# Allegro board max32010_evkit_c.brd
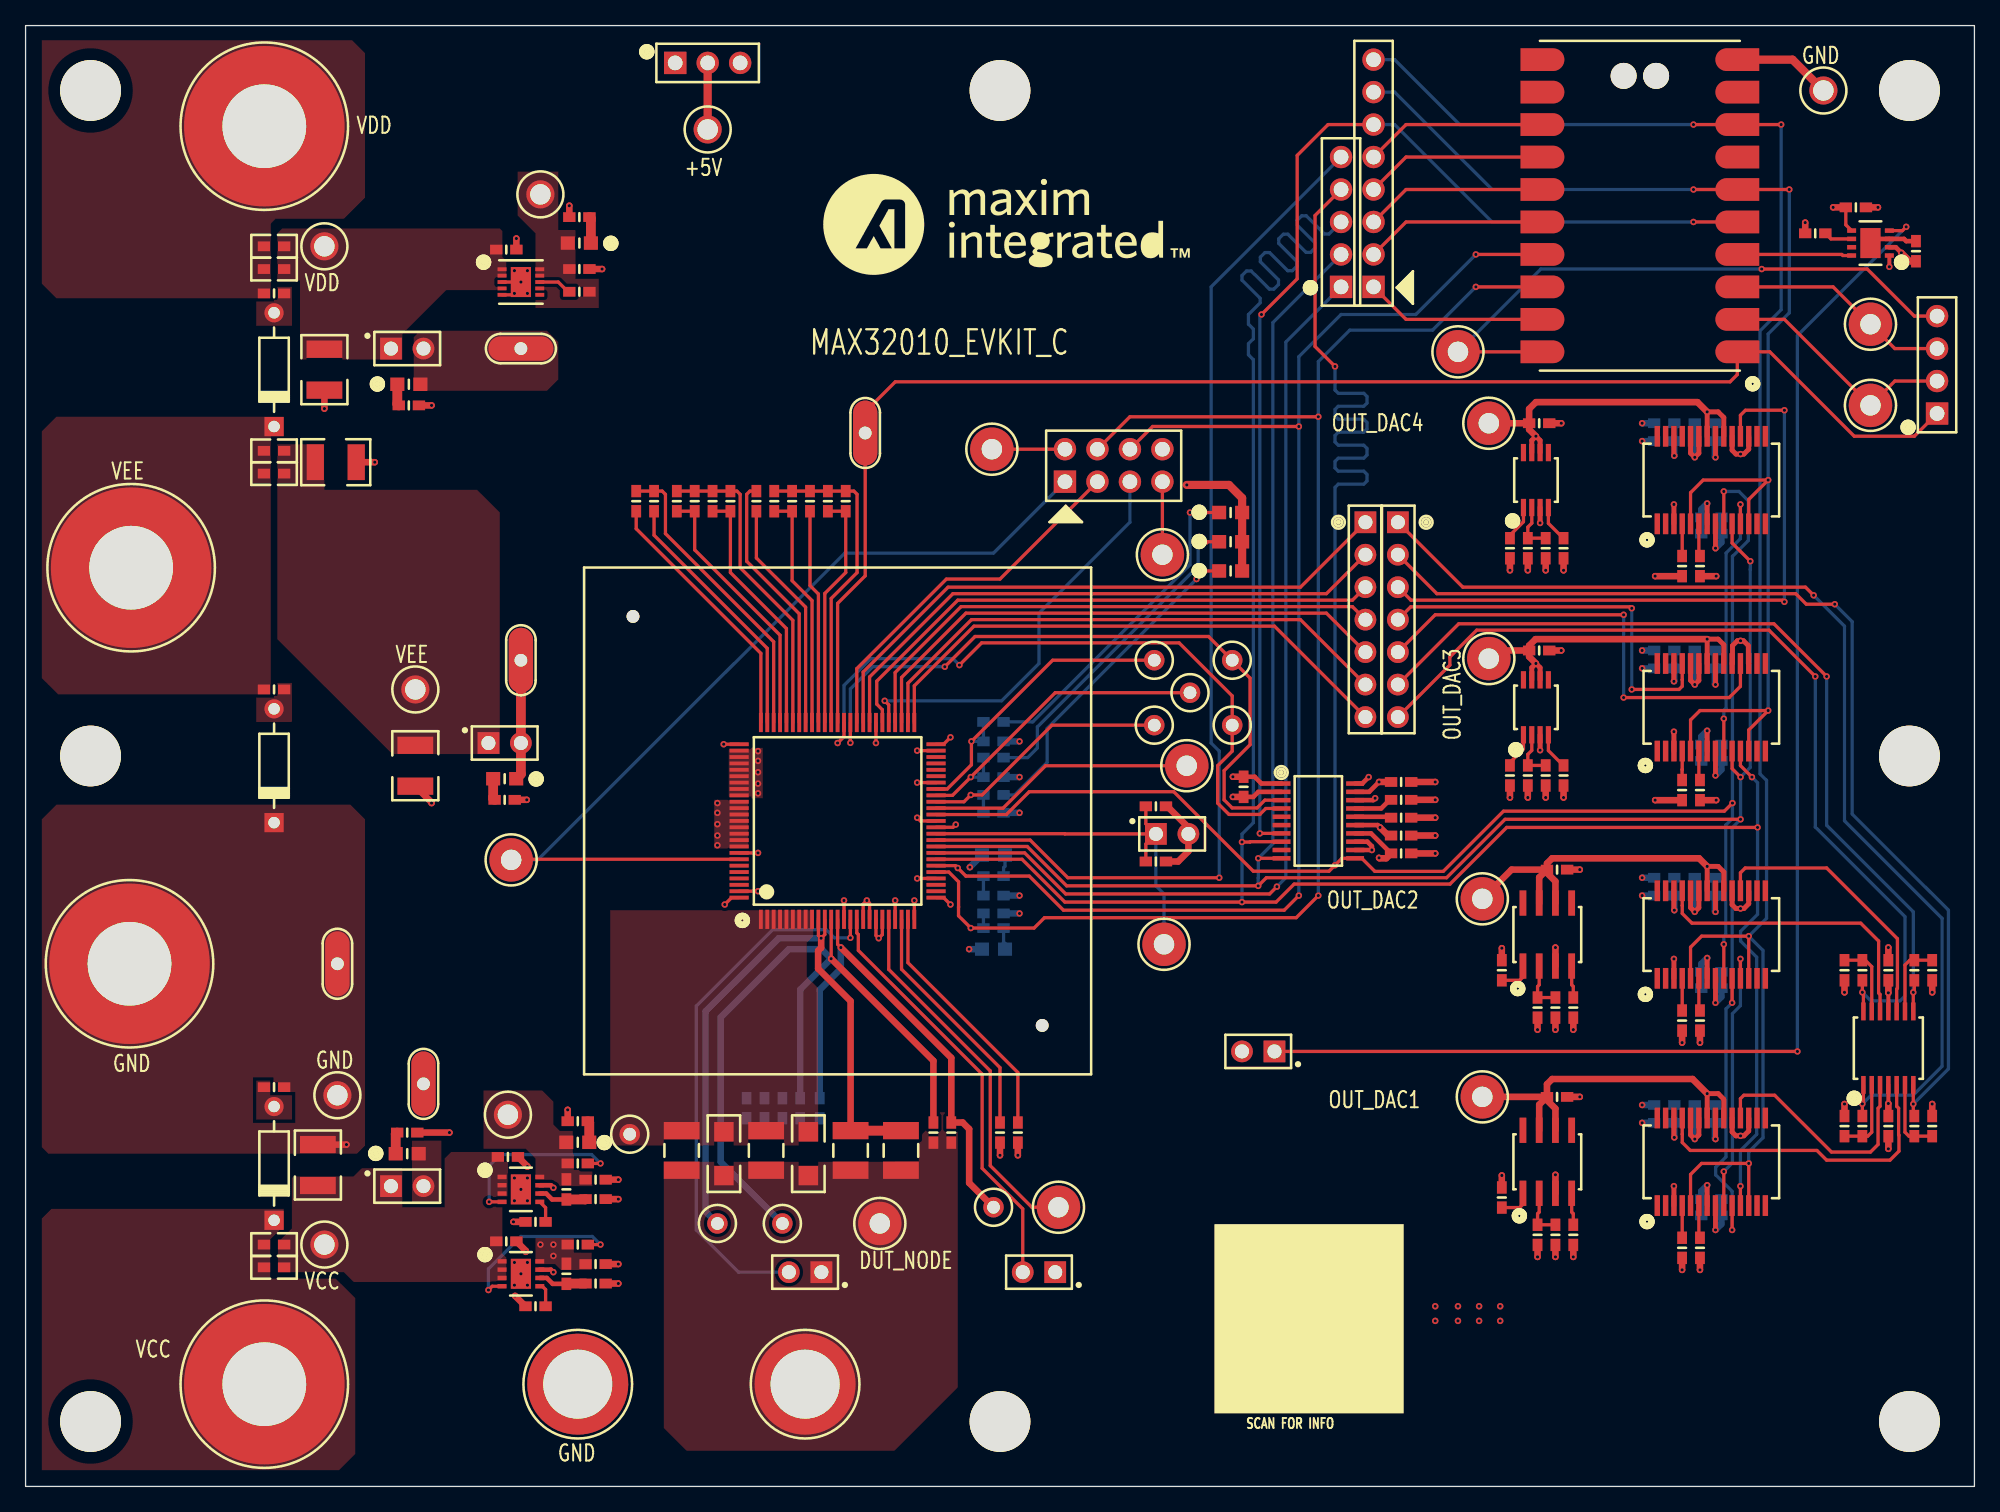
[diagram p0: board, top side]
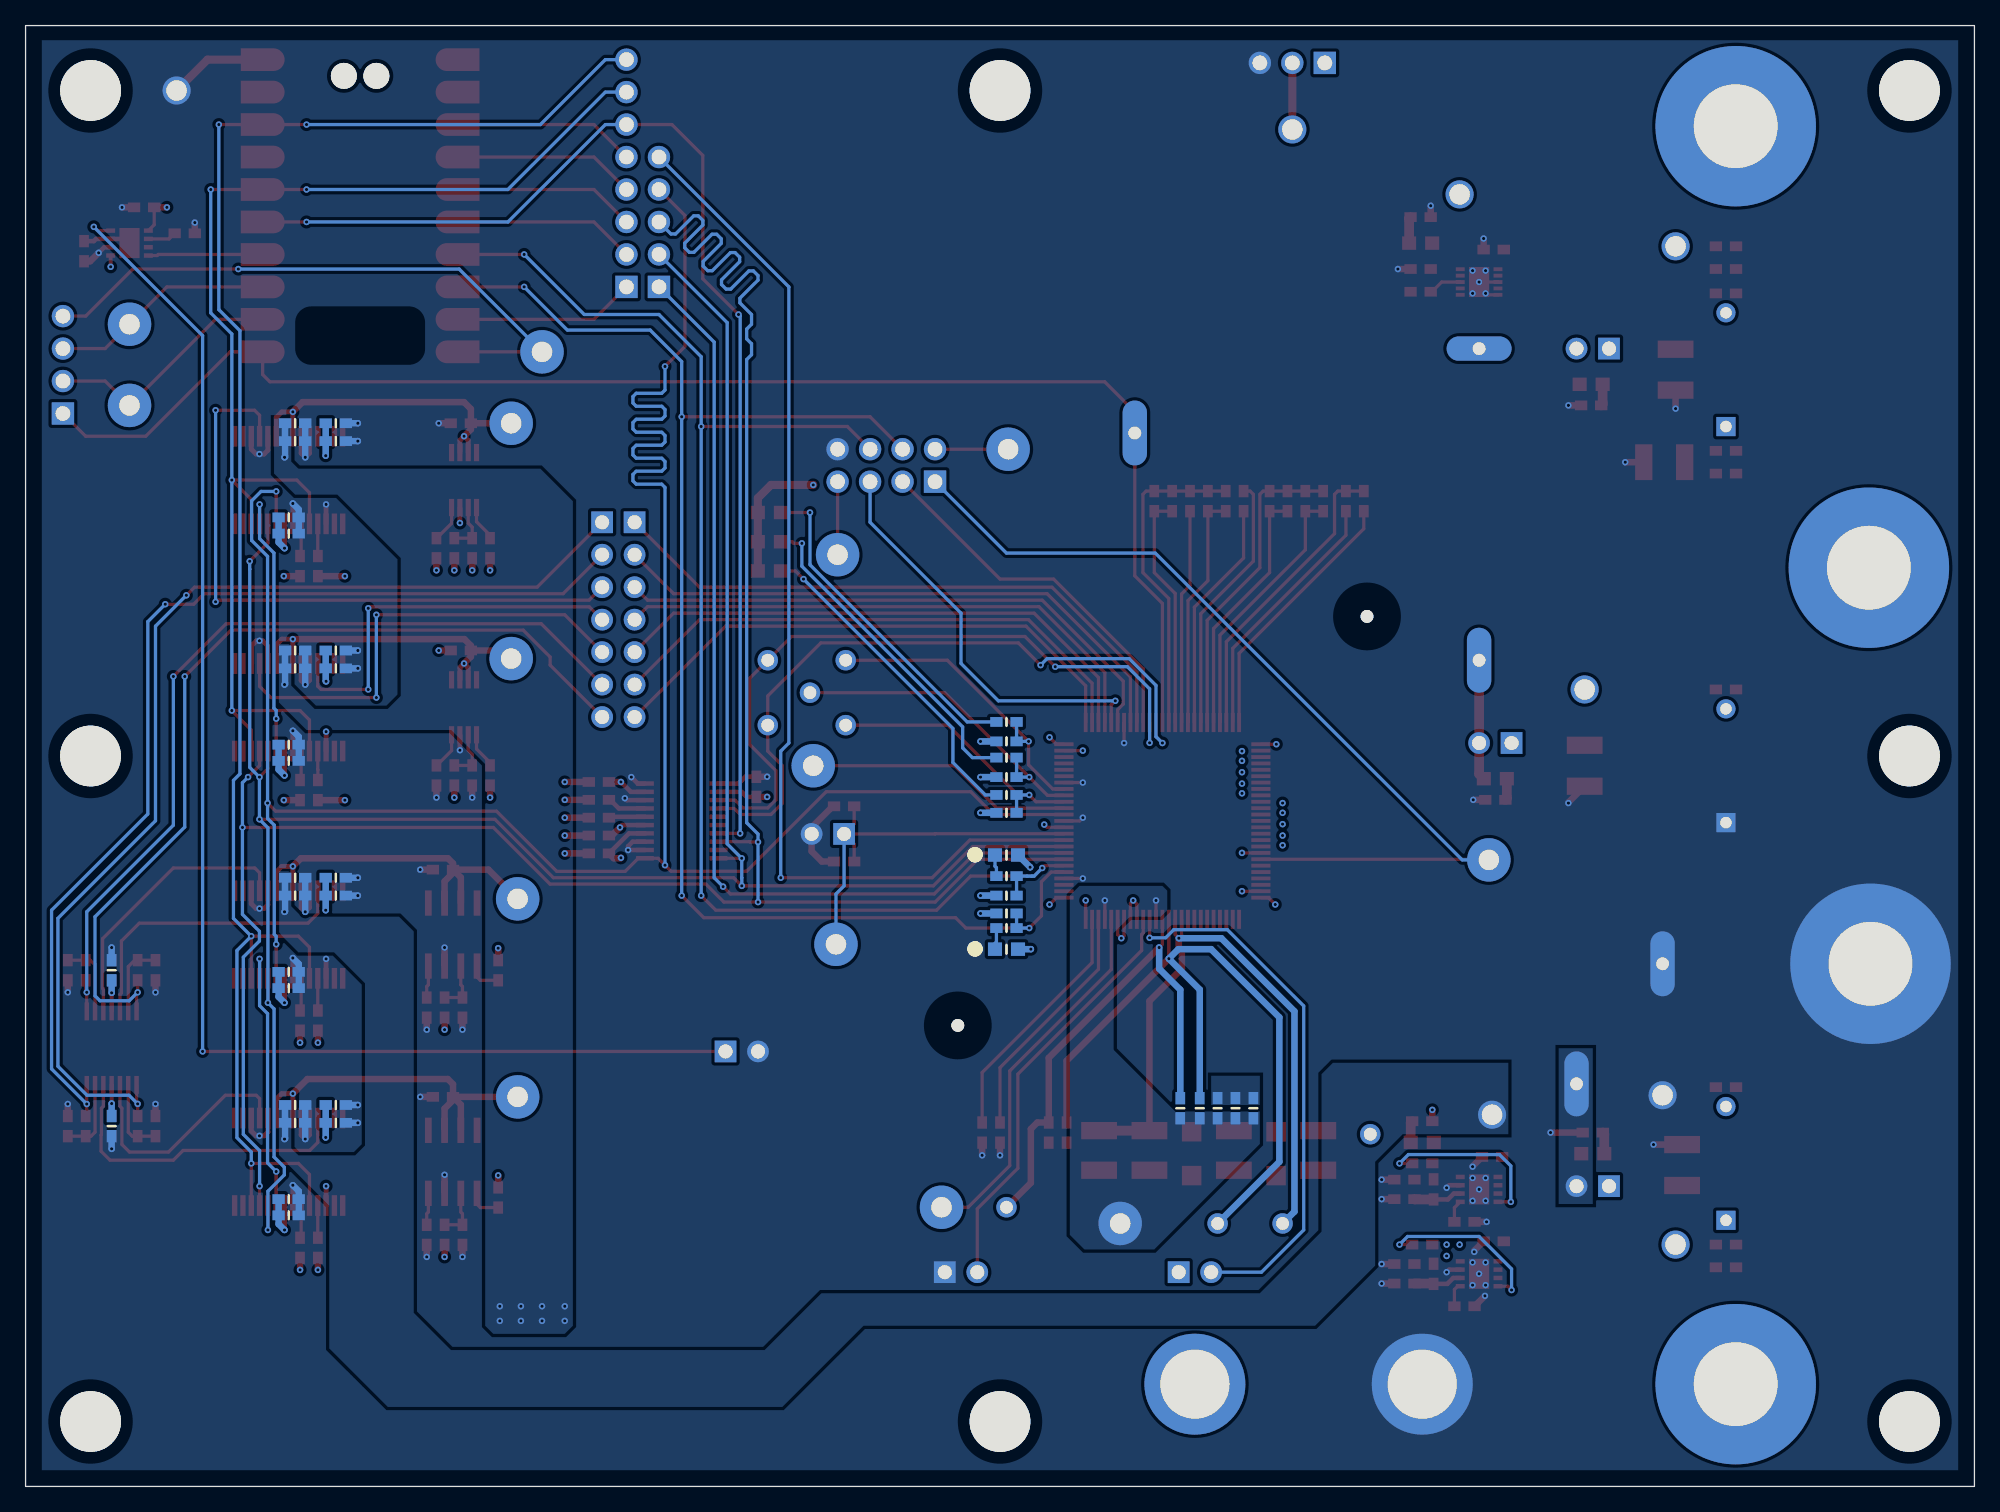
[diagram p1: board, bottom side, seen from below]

Outline 152.4 x 114.3 mm; copper layers: TOP, INTERNAL2, INTERNAL3, BOTTOM. Coordinates in mm from the lower left corner of the outline.
Outline path: rectangle 0,0 152.4,114.3

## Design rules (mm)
constraint set DEFAULT: min track width 0.254
net group MATCH: nets DIN DOUT SCLK

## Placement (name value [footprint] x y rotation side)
AMPOUT  N/A  [KEYS_5012]  37.97 49.02 0 top
C1  10UF  [1210]  22.86 25.15 270 top
C2  10UF  [1210]  30.48 56.39 270 top
C3  10UF  [1210]  24.26 80.14 180 top
C4  1UF  [0603]  37.72 25.78 180 top
C5  1000PF  [0603]  39.88 20.7 0 top
C6  4.7UF  [0603]  44.58 24 180 top
C7  1UF  [0603]  37.59 19.18 180 top
C8  1000PF  [0603]  39.88 14.1 0 top
C9  4.7UF  [0603]  44.58 17.4 180 top
C10  10UF  [0603]  37.59 96.77 180 top
C11  0.047UF  [0603]  43.31 93.47 0 top
C12  10UF  [0603]  43.31 95.25 180 top
C13  10UF  [0603]  118.24 19.68 90 top
C14  10UF  [0603]  118.24 37.47 90 top
C15  10UF  [0603]  117.47 55.63 90 top
C16  10UF  [0603]  117.47 73.41 90 top
C17  0.1UF  [0603]  115.44 22.61 270 top
C18  0.1UF  [0603]  119.76 30.48 180 top
C19  0.1UF  [0603]  115.44 40.39 270 top
C20  0.1UF  [0603]  119.76 48.26 180 top
C21  0.1UF  [0603]  116.08 55.63 90 top
C22  0.1UF  [0603]  118.36 65.41 180 top
C23  0.1UF  [0603]  116.08 73.41 90 top
C24  0.1UF  [0603]  118.36 83.19 180 top
C25  10UF  [0603]  131.83 21.21 0 bottom
C26  10UF  [0603]  131.32 29.84 0 bottom
C27  10UF  [0603]  128.14 29.84 0 bottom
C28  10UF  [0603]  131.83 38.99 0 bottom
C29  10UF  [0603]  131.32 47.62 0 bottom
C30  10UF  [0603]  128.14 47.62 0 bottom
C31  10UF  [0603]  131.83 56.77 0 bottom
C32  10UF  [0603]  131.32 65.41 0 bottom
C33  10UF  [0603]  128.14 65.41 0 bottom
C34  10UF  [0603]  131.83 74.55 0 bottom
C35  10UF  [0603]  131.32 83.19 0 bottom
C36  10UF  [0603]  128.14 83.19 0 bottom
C37  0.1UF  [0603]  131.83 22.48 0 bottom
C38  0.1UF  [0603]  131.32 28.45 0 bottom
C39  0.1UF  [0603]  128.14 28.45 0 bottom
C40  0.1UF  [0603]  131.83 40.26 0 bottom
C41  0.1UF  [0603]  131.32 46.23 0 bottom
C42  0.1UF  [0603]  128.14 46.23 0 bottom
C43  0.1UF  [0603]  131.83 58.04 0 bottom
C44  0.1UF  [0603]  131.32 64.01 0 bottom
C45  0.1UF  [0603]  128.14 64.01 0 bottom
C46  0.1UF  [0603]  131.83 75.82 0 bottom
C47  0.1UF  [0603]  131.32 81.79 0 bottom
C48  0.1UF  [0603]  128.14 81.79 0 bottom
C49  3300PF  [0603]  58.55 77.09 90 top
C50  0.022UF  [0603]  59.94 77.09 90 top
C51  330PF  [0603]  53.72 77.09 270 top
C52  4700PF  [0603]  55.12 77.09 270 top
C53  0.01UF  [0603]  61.34 77.09 90 top
C54  330PF  [0603]  50.93 77.09 270 top
C55  1500PF  [0603]  64.14 77.09 90 top
C56  4700PF  [0603]  52.32 77.09 270 top
C57  100PF  [0603]  49.15 77.09 270 top
C58  1500PF  [0603]  62.74 77.09 90 top
C59  100PF  [0603]  47.75 77.09 270 top
C60  330PF  [0603]  57.15 77.09 270 top
C61  270PF  [0603]  77.6 27.69 270 top
C62  270PF  [0603]  76.2 27.69 270 top
C63  4.7UF  [0603]  145.67 28.19 90 bottom
C64  0.1UF  [0603]  145.67 28.19 90 top
C65  4.7UF  [0603]  145.67 40.39 270 bottom
C66  0.1UF  [0603]  145.67 40.39 270 top
C67  0.1UF  [0603]  147.83 96.65 90 top
C68  0.1UF  [0603]  139.95 98.04 0 top
C69  1UF  [0603]  143.13 100.08 180 top
C70  0.1UF  [0603]  95.25 54.74 270 top
C71  0.1UF  [0603]  107.57 49.53 180 top
C72  0.1UF  [0603]  107.57 50.93 180 top
C73  0.1UF  [0603]  107.57 55.12 180 top
C74  1UF  [0603]  107.57 52.32 180 top
C75  1UF  [0603]  107.57 53.72 180 top
C76  10UF  [1210]  23.37 87.38 90 top
D1  20V  [DO-35]  19.43 25.27 90 top
D2  20V  [DO-35]  19.43 56.39 90 top
D3  20V  [DO-35]  19.43 87.38 90 top
DS1  LTST-C190CKT  [LEDC1608X80M]  94.23 76.2 0 top
DS2  LTST-C190CKT  [LEDC1608X80M]  94.23 73.91 0 top
DS3  LTST-C190CKT  [LEDC1608X80M]  94.23 71.63 0 top
DS4  LTST-C193KGKT-5A  [LEDC1608X80M]  75.69 49.4 180 bottom
DS5  LTST-C193KGKT-5A  [LEDC1608X80M]  75.69 42.04 180 bottom
DS6  LTST-C193KGKT-5A  [LEDC1608X80M]  29.84 26.04 0 top
DS8  LTST-C193KGKT-5A  [LEDC1608X80M]  37.47 55.37 180 top
DS9  LTST-C193KGKT-5A  [LEDC1608X80M]  43.18 26.92 180 top
DS10  LTST-C193KGKT-5A  [LEDC1608X80M]  43.31 97.28 180 top
DS11  LTST-C193KGKT-5A  [LEDC1608X80M]  29.97 86.23 0 top
DUT_NODE  575-4  [KEYSTONE_575]  60.96 8 90 top
EXTSEL  N/A  [KEYS_5012]  90.81 56.39 0 top
FB1  220  [0603]  19.43 18.92 0 top
FB2  220  [0603]  19.43 17.14 0 top
FB3  220  [0603]  19.43 81.03 0 top
FB4  220  [0603]  19.43 79.25 0 top
FB5  220  [0603]  19.43 95.25 0 top
FB6  220  [0603]  19.43 97.03 0 top
GND  MAXIMPAD  [EVK_MAXIMPAD]  24.38 40.89 90 top
HITEMP  N/A  [KEYS_5000]  88.27 59.56 0 top
HITMP  N/A  [KEYS_5012]  112.01 88.77 0 top
ILIMHI  N/A  [KEYS_5000]  88.27 64.64 0 top
ILIMLO  N/A  [KEYS_5000]  91.06 62.1 0 top
IMEAS  N/A  [KEYS_5002]  94.36 64.64 0 top
J1  PCC02SAAN  [SULLINS_PXC02S]  62.23 16.76 180 top
J2  PCC02SAAN  [SULLINS_PXC02S]  80.52 16.76 180 top
J3  PCC02SAAN  [SULLINS_PXC02S]  88.39 51.05 0 top
J4  PBC04DAAN  [SULLINS_PXC04DAAN]  81.28 78.61 0 top
J5  PEC03SAAN  [SULLINS_PXC03SAAN]  50.8 111.38 0 top
J6  PCC02SAAN  [SULLINS_PXC02S]  97.66 34.04 180 top
J7  PCC02SAAN  [SULLINS_PXC02S]  28.57 23.5 0 top
J8  PCC02SAAN  [SULLINS_PXC02S]  36.2 58.17 0 top
J9  PCC02SAAN  [SULLINS_PXC02S]  28.57 89.03 0 top
J10  ATS-61400D-C1-R0  [EK_ATSI_ATS-61400D-C1-R0]  63.5 52.07 0 top
J11  PBC04SAAN  [SULLINS_PXC04SAAN]  149.48 83.95 90 top
J12  PBC08SAAN  [SULLINS_PXC08SAAN]  105.41 93.85 90 top
J13  PBC05SAAN  [SULLINS_PXC05SAAN]  102.87 93.85 90 top
J14  PEC07SAAN  [SULLINS_PXC07S]  104.78 75.44 270 top
J15  PEC07SAAN  [SULLINS_PXC07S]  107.31 75.44 270 top
MH1  9032  [KEYS_9032]  5.08 109.22 180 bottom
MH2  9032  [KEYS_9032]  147.32 109.22 180 bottom
MH3  9032  [KEYS_9032]  5.08 5.08 180 bottom
MH4  9032  [KEYS_9032]  147.32 5.08 180 bottom
MH5  9032  [KEYS_9032]  76.2 5.08 180 bottom
MH6  9032  [KEYS_9032]  76.2 109.22 180 bottom
MH7  9032  [KEYS_9032]  5.08 57.15 180 bottom
MH8  9032  [KEYS_9032]  147.32 57.15 180 bottom
MISC1  3025010-03  [EVKIT_CABLES]  84.58 -8.13 0 top
NOREF  -  []  161.29 11.43 0 top
NOREF#2  -  []  92.96 5.71 0 top
NOREF#3  -  []  44.17 -25.4 0 top
NOREF#4  -  []  51.73 -3.17 0 top
NOREF#5  -  []  0 114.3 0 top
NOREF#6  -  []  74.75 150.26 0 top
NOREF#7  -  []  2.35 2.5 0 top
NOREF#8  -  []  99.06 79.41 0 top
NOREF#9  -  []  93.34 71.12 0 top
NOREF#10  -  []  152.4 0 90 top
NOREF#11  -  []  12.7 -12.7 0 top
NOREF#12  -  []  73.66 86.46 0 top
NOREF#13  -  []  6.35 -25.4 0 top
NOREF#14  -  []  66.35 98.64 0 top
NOREF#15  -  []  6.35 -25.4 180 bottom
R1  OPEN  [0603]  19.43 31.24 0 top
R2  OPEN  [0603]  19.43 62.36 180 top
R3  OPEN  [0603]  19.43 93.34 180 top
R4  390K  [0603]  42.29 23.24 270 top
R5  50K  [0603]  44.58 22.48 0 top
R6  10K  [0603]  43.18 25.27 0 top
R7  390K  [0603]  42.29 16.64 270 top
R8  50K  [0603]  44.58 15.88 0 top
R9  10K  [0603]  43.18 18.92 0 top
R10  0  [0603]  119.63 19.68 90 top
R11  0  [0603]  121.03 19.68 270 top
R12  0  [0603]  119.63 37.47 90 top
R13  0  [0603]  121.03 37.47 270 top
R14  1K  [0603]  118.87 55.63 90 top
R15  0  [0603]  120.27 55.63 270 top
R16  1K  [0603]  118.87 73.41 90 top
R17  0  [0603]  120.27 73.41 270 top
R18  22K  [0603]  130.94 18.67 90 top
R19  22K  [0603]  129.54 18.67 90 top
R20  22K  [0603]  130.94 36.45 90 top
R21  22K  [0603]  129.54 36.45 90 top
R22  22K  [0603]  130.94 54.48 90 top
R23  22K  [0603]  129.54 54.48 90 top
R24  22K  [0603]  130.94 72.01 90 top
R25  22K  [0603]  129.54 72.01 90 top
R26  OPEN  [0603]  56.39 29.59 90 bottom
R27  OPEN  [0603]  57.78 29.59 90 bottom
R28  OPEN  [0603]  59.18 29.59 90 bottom
R29  OPEN  [0603]  88.39 48.9 180 top
R30  OPEN  [0603]  88.39 53.21 0 top
R31  10  [RESC3225X65M]  51.31 26.29 270 top
R32  1.54  [1206]  54.61 26.04 270 top
R33  10  [RESC3225X65M]  57.91 26.29 270 top
R34  1.54  [1206]  61.21 26.04 270 top
R35  1K  [0603]  70.99 27.69 270 top
R36  10K  [0603]  72.39 27.69 90 top
R37  100  [RESC3225X65M]  64.52 26.29 270 top
R38  100  [RESC3225X65M]  68.45 26.29 270 top
R39  1K  [0603]  60.58 29.59 270 bottom
R40  10K  [0603]  62.1 29.59 90 bottom
R41  10K  [0603]  75.69 58.29 180 bottom
R42  1K  [0603]  75.69 59.82 180 bottom
R43  10K  [0603]  75.69 55.5 180 bottom
R44  1K  [0603]  75.69 57.02 180 bottom
R45  10K  [0603]  75.69 52.7 180 bottom
R46  10K  [0603]  75.69 46.23 180 bottom
R47  1K  [0603]  75.69 54.1 180 bottom
R48  1K  [0603]  75.69 47.75 180 bottom
R49  10K  [0603]  75.69 44.83 180 bottom
R50  1K  [0603]  75.69 43.69 180 bottom
R51  3.3K  [0603]  29.84 27.69 0 top
R53  1K  [0603]  29.97 84.58 0 top
R54  2.7K  [0603]  43.18 28.57 180 top
R55  1K  [0603]  43.31 99.31 180 top
R56  3.48K  [0603]  149.1 28.19 270 top
R57  3.48K  [0603]  142.24 28.19 270 top
R58  2K  [0603]  147.7 28.19 90 top
R59  2K  [0603]  143.64 28.19 90 top
R60  3.48K  [0603]  149.1 40.39 90 top
R61  3.48K  [0603]  142.24 40.39 90 top
R62  2K  [0603]  147.7 40.39 270 top
R63  2K  [0603]  143.64 40.39 270 top
R68  2.7K  [0603]  37.47 53.72 0 top
RA  N/A  [KEYS_5000]  47.24 27.56 90 top
RB  N/A  [KEYS_5000]  54.1 20.57 90 top
RC  N/A  [KEYS_5000]  59.18 20.57 90 top
RD  N/A  [KEYS_5000]  75.69 21.84 90 top
SU1  NPC02SXON-RC  [EVKIT_SHUNT]  140.64 -23.73 0 top
SU2  NPC02SXON-RC  [EVKIT_SHUNT]  121.87 -23.73 0 top
SU3  NPC02SXON-RC  [EVKIT_SHUNT]  112.49 -23.73 0 top
SU4  NPC02SXON-RC  [EVKIT_SHUNT]  103.11 -23.73 0 top
SU5  NPC02SXON-RC  [EVKIT_SHUNT]  93.73 -23.73 0 top
SU6  NPC02SXON-RC  [EVKIT_SHUNT]  74.97 -23.73 0 top
SU7  NPC02SXON-RC  [EVKIT_SHUNT]  65.59 -23.73 0 top
SU8  NPC02SXON-RC  [EVKIT_SHUNT]  84.35 -23.73 0 top
SU9  NPC02SXON-RC  [EVKIT_SHUNT]  131.26 -23.73 0 top
SU10  NPC02SXON-RC  [EVKIT_SHUNT]  65.59 -29.12 0 top
SU11  NPC02SXON-RC  [EVKIT_SHUNT]  74.97 -29.12 0 top
SU12  NPC02SXON-RC  [EVKIT_SHUNT]  84.35 -29.12 0 top
SU13  NPC02SXON-RC  [EVKIT_SHUNT]  93.73 -29.12 0 top
SU14  NPC02SXON-RC  [EVKIT_SHUNT]  103.11 -29.12 0 top
SU15  NPC02SXON-RC  [EVKIT_SHUNT]  112.49 -29.12 0 top
SU16  NPC02SXON-RC  [EVKIT_SHUNT]  121.87 -29.12 0 top
SU17  NPC02SXON-RC  [EVKIT_SHUNT]  131.26 -29.12 0 top
SU18  NPC02SXON-RC  [EVKIT_SHUNT]  140.64 -29.12 0 top
SU19  NPC02SXON-RC  [EVKIT_SHUNT]  150.02 -29.12 0 top
SU20  NPC02SXON-RC  [EVKIT_SHUNT]  159.4 -29.12 0 top
SU21  NPC02SXON-RC  [EVKIT_SHUNT]  168.78 -29.12 0 top
TEMP  MAXIMPAD  [EVK_MAXIMPAD]  65.66 82.42 90 top
TP1  3267  [POMONA_3267]  18.67 8 0 top
TP2  3267  [POMONA_3267]  8.13 40.89 0 top
TP3  3267  [POMONA_3267]  8.26 71.88 180 top
TP4  3267  [POMONA_3267]  18.67 106.43 180 top
TP5  N/A  [KEYS_5005]  23.37 18.92 0 top
TP6  N/A  [KEYS_5006]  24.38 30.61 0 top
TP7  N/A  [KEYS_5006]  30.48 62.36 0 top
TP8  N/A  [KEYS_5005]  23.37 97.03 0 top
TP9  N/A  [KEYS_5012]  113.92 30.48 90 top
TP10  N/A  [KEYS_5012]  113.92 45.97 90 top
TP11  N/A  [KEYS_5012]  114.43 64.77 90 top
TP12  N/A  [KEYS_5012]  114.43 83.19 90 top
TP13  N/A  [KEYS_5012]  66.8 20.57 90 top
TP14  575-4  [KEYSTONE_575]  43.18 8 90 top
TP17  N/A  [KEYS_5012]  144.27 84.58 0 top
TP18  N/A  [KEYS_5012]  144.27 90.93 0 top
TP19  N/A  [KEYS_5012]  88.9 72.9 0 top
TP20  N/A  [KEYS_5012]  75.56 81.15 0 top
TP21  N/A  [KEYS_5006]  140.59 109.22 0 top
TP22  N/A  [KEYS_5005]  53.34 106.17 0 top
U1  MAX16910CATA8+  [MAXIM_90-0059]  38.73 23.24 0 top
U2  MAX16910CATA8+  [MAXIM_90-0059]  38.73 16.64 0 top
U3  MAX38903AATB+  [MAXIM_90-0003]  38.73 94.23 0 top
U4  MAX6126AASA50+  [MAXIM_90-0096]  119 25.4 90 top
U5  MAX6126AASA50+  [MAXIM_90-0096]  119 43.18 90 top
U6  MAX6126B21+  [MAXIM_90-0092]  118.11 60.96 90 top
U7  MAX6126B21+  [MAXIM_90-0092]  118.11 78.74 90 top
U8  MAX5322EAI+  [MAXIM_90-0095]  131.83 25.4 90 top
U9  MAX5322EAI+  [MAXIM_90-0095]  131.83 43.18 90 top
U10  MAX5322EAI+  [MAXIM_90-0095]  131.83 60.96 90 top
U11  MAX5322EAI+  [MAXIM_90-0095]  131.83 78.74 90 top
U12  MAX32010  [MAXIM_90-0159]  63.5 52.07 90 top
U13  MAX32625PICO  [MOD_MAX32625PICO_20P]  126.24 100.2 180 top
U14  MAX44245AUD+  [MAXIM_90-0113]  145.67 34.29 90 top
U15  MAX14759ETA+  [MAXIM_90-0059]  144.27 97.28 180 top
U16  MAX1033BEUP+  [MAXIM_90-0116]  101.09 52.07 0 top
VCC  MAXIMPAD  [EVK_MAXIMPAD]  31.11 31.5 90 top
VDAC  N/A  [KEYS_5005]  37.72 29.08 0 top
VDD  MAXIMPAD  [EVK_MAXIMPAD]  38.73 89.03 180 top
VEE  MAXIMPAD  [EVK_MAXIMPAD]  38.73 64.64 90 top
VL  N/A  [KEYS_5005]  40.26 101.09 0 top
VMEAS  N/A  [KEYS_5002]  94.36 59.56 0 top
VRXP  N/A  [KEYS_5012]  80.77 21.84 90 top
VTHR  N/A  [KEYS_5012]  89.03 42.42 0 top

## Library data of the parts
AMPOUT EXTSEL HITMP TP9-TP13 TP17-TP20 VRXP VTHR = TP: part number: TP_TP-KEYS_5012,N/A,02-TPMINI5012-00
C1-C3 C76 = CAP_NP: alternate symbols: CAPC3225X270L,CAP1210-NOT_FOR_TEST; part number: CAP_NP_1210CAP-1210,10UF,20-0010U-G9
C4 C7 C69 C74 C75 = CAP_NP: alternate symbols: 0603_NOSILK,CAPC1608X90L,CAP0603-NOT_FOR_TEST; part number: CAP_NP_0603CAP-0603,1UF,20-0001U-P6
C5 C8 = CAP_NP: alternate symbols: 0603_NOSILK,CAPC1608X90L,CAP0603-NOT_FOR_TEST; part number: CAP_NP_0603CAP-0603,1000PF,20-1000P-E4
C6 C9 C63 C65 = CAP_NP: alternate symbols: 0603_NOSILK,CAPC1608X90L; part number: CAP_NP_0603CAP-0603,4.7UF,20-004U7-L3
C10 C12-C16 C25-C36 = CAP_NP: alternate symbols: 0603_NOSILK,CAPC1608X90L,CAP0603-NOT_FOR_TEST; part number: CAP_NP_0603CAP-0603,10UF,20-0010U-P7
C11 = CAP_NP: alternate symbols: 0603_NOSILK,CAPC1608X90L,CAP0603-NOT_FOR_TEST; part number: CAP_NP_0603CAP-0603,0.047UF,20-0U047-91
C17-C24 C37-C48 C64 C66-C68 C70-C73 = CAP_NP: alternate symbols: 0603_NOSILK,CAPC1608X90L,CAP0603-NOT_FOR_TEST; part number: CAP_NP_0603CAP-0603,0.1UF,20-000U1-EA01
C49 = CAP_NP: alternate symbols: 0603_NOSILK,CAPC1608X90L; part number: CAP_NP_0603CAP-0603,3300PF,20-3300P-BA63
C50 = CAP_NP: alternate symbols: 0603_NOSILK,CAPC1608X90L,CAP0603-NOT_FOR_TEST; part number: CAP_NP_0603CAP-0603,0.022UF,20-0U022-91
C51 C54 C60 = CAP_NP: alternate symbols: 0603_NOSILK,CAPC1608X90L; part number: CAP_NP_0603CAP-0603,330PF,20-0330P-14B
C52 C56 = CAP_NP: alternate symbols: (0603_NOSILK); part number: CAP_NP_0603CAP-0603,4700PF,20-4700P-91
C53 = CAP_NP: alternate symbols: 0603_NOSILK,CAPC1608X90L; part number: CAP_NP_0603CAP-0603,0.01UF,20-00U01-B70
C55 C58 = CAP_NP: alternate symbols: (0603_NOSILK); part number: CAP_NP_0603CAP-0603,1500PF,20-1500P-91
C57 C59 = CAP_NP: alternate symbols: 0603_NOSILK,CAPC1608X90L; part number: CAP_NP_0603CAP-0603,100PF,20-0100P-15
C61 C62 = CAP_NP: alternate symbols: (0603_NOSILK); part number: CAP_NP_0603CAP-0603,270PF,20-0270P-77
D1-D3 = DIO_ZENER: part number: DIO_ZENER_DO-35-DO-35,20V,30-1N5250B-00
DS1-DS3 = LED: part number: LED_LEDC1608X80M-LEDC1608X80M,LTST-C190CKT,30-LTSTC190CKT-00
DS4-DS6 DS8-DS11 = LED: part number: LED_LEDC1608X80M-LEDC1608X80M,LTST-C193KGKT-5A,30-LTSTC193KGKT5A-00
DUT_NODE TP14 = BANANA: part number: BANANA_TMR-KEYSTONE_575,575-4,02-57541P-01
FB1-FB6 = FERRITEBEAD: alternate symbols: INDC1608X65L; part number: FERRITEBEAD_0603-0603,220,51-00220-0AV
GND TEMP VCC VDD VEE = EVK_MAXIMPAD: alternate symbols: EVK_MAXIMPAD_ALT; part number: EVK_MAXIMPAD_MISC-EVK_MAXIMPAD,MAXIMPAD,01-9020BUSS20AWG-00
HITEMP ILIMHI ILIMLO RA RB RC RD = TP: part number: TP_TP-KEYS_5000,N/A,02-TPMINI5000-00
IMEAS VMEAS = TP: part number: TP_TP-KEYS_5002,N/A,02-TPMINI5002-00
J1-J3 J6-J9 = HEADER_2P: part number: HEADER_2P_PXC02S-SULLINS_PXC02S,PCC02SAAN,01-PCC02SAAN2P-21
J4 = HEADER_4P_X_2R: part number: HEADER_4P_X_2R_TH-SULLINS_PXC04DAAN,PBC04DAAN,01-PBC04DAAN8P-21
J5 = HEADER_3P: alternate symbols: SULLINS_PXC03SL; part number: HEADER_3P_TH-SULLINS_PXC03SAAN,PEC03SAAN,01-PEC03SAAN3P-21
J10 = EK_HEAT_SINK: part number: EK_HEAT_SINK_ASSEMBLY-EK_ATSI_ATS-61400D-C1-R0,ATS-61400D-C1-R0,EH111000005579
J11 = HEADER_4P: part number: HEADER_4P_TH-SULLINS_PXC04SAAN,PBC04SAAN,01-PBC04SAAN4P-21
J12 = HEADER_8P: part number: HEADER_8P_TH-SULLINS_PXC08SAAN,PBC08SAAN,01-PBC08SAAN8P-21
J13 = HEADER_5P: part number: HEADER_5P_TH-SULLINS_PXC05SAAN,PBC05SAAN,01-PBC05SAAN5P-21
J14 J15 = HEADER_7P: part number: HEADER_7P_PXC07S-SULLINS_PXC07S,PEC07SAAN,01-PEC07SAAN7P-21
MH1-MH8 = SPACER: part number: SPACER_MECH-02-SOM35016H-00,9032,KEYS_9032
MISC1 = CABLES: part number: CABLES_MISC-01-302501003-10,3025010-03,EVKIT_CABLES
R1-R3 R26-R30 = EVK_GENERIC_RESISTORS: alternate symbols: 0603_NOSILK,RESC1608X90L; part number: EVK_GENERIC_RESISTORS_0603RES-0603,N/A
R4 R7 = RES: alternate symbols: (0603_NOSILK); part number: RES_0603RES-0603,390K,80-0390K-53
R5 R8 = RES: alternate symbols: 0603_NOSILK,RESC1608X90L; part number: RES_0603RES-0603,50K,80-0050K-AA99
R6 R9 R36 R40 = RES: alternate symbols: 0603_NOSILK,RESC1608X90L; part number: RES_0603RES-0603,10K,80-0010K-24
R10-R13 R15 R17 = RES: alternate symbols: 0603_NOSILK,RESC1608X90L; part number: RES_0603RES-0603,0,80-0000R-AA6
R14 R16 R35 R39 R42 R44 R47 R48 R50 = RES: alternate symbols: 0603_NOSILK,RESC1608X90L; part number: RES_0603RES-0603,1K,80-0001K-24
R18-R25 = RES: alternate symbols: (0603_NOSILK); part number: RES_0603RES-0603,22K,80-0022K-24
R31 R33 = RES: alternate symbols: RESC3225X70L; part number: RES_1210RES-RESC3225X65M,10,80-0010R-DA02
R32 R34 = RES: alternate symbols: RESC3116X60L; part number: RES_1206RES-1206,1.54,ER111000003584
R37 R38 = RES: alternate symbols: RESC3225X70L; part number: RES_1210RES-RESC3225X65M,100,80-0100R-BA01
R41 R43 R45 R46 R49 = RES: alternate symbols: (0603_NOSILK); part number: RES_0603RES-0603,10K,80-0010K-77
R51 = RES: alternate symbols: 0603_NOSILK,RESC1608X90L; part number: RES_0603RES-0603,3.3K,80-003K3-24
R53 R55 = RES: alternate symbols: 0603_NOSILK,RESC1608X90L; part number: RES_0603RES-0603,1K,80-0001K-53
R54 R68 = RES: alternate symbols: 0603_NOSILK,RESC1608X90L; part number: RES_0603RES-0603,2.7K,80-002K7-24
R56 R57 R60 R61 = RES: alternate symbols: 0603_NOSILK,RESC1608X90L; part number: RES_0603RES-0603,3.48K,80-03K48-AA4
R58 R59 R62 R63 = RES: alternate symbols: (0603_NOSILK); part number: RES_0603RES-0603,2K,80-0002K-19
SU1-SU21 = SHUNT: part number: SHUNT_SHUNT_2P-01-NPC02SXON2P-24,NPC02SXON-RC,EVKIT_SHUNT
TP1-TP4 = BANANA: alternate symbols: POMONA_3267_LUG_HEAD,POMONA_3267_LUG_NUT; part number: BANANA_3267-POMONA_3267,3267,01-32671P-80
TP5 TP8 TP22 VDAC VL = TP: part number: TP_TP-KEYS_5005,N/A,02-TPCOMP5005-00
TP6 TP7 TP21 = TP: part number: TP_TP-KEYS_5006,N/A,02-TPCOMP5006-00
U1 U2 = MAX16910: part number: MAX16910_TDFN8-EP-MAXIM_90-0059,MAX16910CATA8+,10-MAX16910CATA8-T
U3 = EK_MAX38903: part number: EK_MAX38903_TDFN10-EP-MAXIM_90-0003,MAX38903AATB+,N/A
U4 U5 = MAX6126: part number: MAX6126_SOIC-MAXIM_90-0096,MAX6126AASA50+,10-MAX6126AASA50-S
U6 U7 = MAX6126: part number: MAX6126_UMAX8-MAXIM_90-0092,MAX6126B21+,10-MAX6126B21-U
U8-U11 = MAX5322: part number: MAX5322_SSOP28-MAXIM_90-0095,MAX5322EAI+,10-MAX5322EAI-A
U12 = EK_MAX32010: part number: EK_MAX32010_TQFP100-MAXIM_90-0159,MAX32010,N/A
U13 = MAX32625PICO: part number: MAX32625PICO_MOD_20P-MOD_MAX32625PICO_20P,MAX32625PICO,10-MODMAX32625PICO-00
U14 = MAX44245: part number: MAX44245_SPLIT_TSSOP14-MAXIM_90-0113,MAX44245AUD+,10-MAX44245AUD-U
U15 = MAX14759: part number: MAX14759_TDFN8-EP-MAXIM_90-0059,MAX14759ETA+,10-MAX14759ETA-T
U16 = MAX1033: part number: MAX1033_TSSOP-MAXIM_90-0116,MAX1033BEUP+,10-MAX1033BEUP-U

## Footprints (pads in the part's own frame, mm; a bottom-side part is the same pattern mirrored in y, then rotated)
0603
  rect 0.965x0.762 smd: 1(-0.787,0) 2(0.787,0)
1206
  rect 1.524x1.524 smd: 1(-1.714,0) 2(1.714,0)
1210
  rect 1.35x2.8 smd: 1(-1.6,0) 2(1.6,0)
DO-35
  round 1.5 hole 0.9: A(4.45,0)
  rect 1.5x1.5 hole 0.9: C(-4.45,0)
EK_ATSI_ATS-61400D-C1-R0
  round 1 hole 4.3 unplated: (-16,16) (16,-16)
EVK_MAXIMPAD
  oval 5.08x1.905 hole 1: 1(0,0)
KEYS_5000
  round 1.6 hole 1: 1(0,0)
KEYS_5002
  round 1.6 hole 1: 1(0,0)
KEYS_5005
  round 2.2 hole 1.6: 1(0,0)
KEYS_5006
  round 2.2 hole 1.6: 1(0,0)
KEYS_5012
  round 3.4 hole 1.6: 1(0,0)
KEYS_9032
  round 4.75 hole 4.75 unplated: (0,0)
KEYSTONE_575
  round 7.9 hole 5.4: 1(0,0)
LEDC1608X80M
  rect 1.1x1.05 smd: A(0.9,0) K(-0.9,0)
MAXIM_90-0003
  rect 0.7x0.3 smd: 1(-1.475,1) 2(-1.475,0.5) 3(-1.475,0) 4(-1.475,-0.5) 5(-1.475,-1) 6(1.475,-1) 7(1.475,-0.5) 8(1.475,0) 9(1.475,0.5) 10(1.475,1)
  rect 1.58x2.35 smd: 11(0,0)
MAXIM_90-0059
  rect 0.7x0.35 smd: 1(-1.475,0.975) 2(-1.475,0.325) 3(-1.475,-0.325) 4(-1.475,-0.975) 5(1.475,-0.975) 6(1.475,-0.325) 7(1.475,0.325) 8(1.475,0.975)
  rect 1.58x2.35 smd: 9(0,0)
MAXIM_90-0092
  rect 1.35x0.4 smd: 1(-2.15,0.975) 2(-2.15,0.325) 3(-2.15,-0.325) 4(-2.15,-0.975) 5(2.15,-0.975) 6(2.15,-0.325) 7(2.15,0.325) 8(2.15,0.975)
MAXIM_90-0095
  rect 1.62x0.42 smd: 1(-3.425,4.225) 2(-3.425,3.575) 3(-3.425,2.925) 4(-3.425,2.275) 5(-3.425,1.625) 6(-3.425,0.975) 7(-3.425,0.325) 8(-3.425,-0.325) 9(-3.425,-0.975) 10(-3.425,-1.625) 11(-3.425,-2.275) 12(-3.425,-2.925) 13(-3.425,-3.575) 14(-3.425,-4.225) 15(3.425,-4.225) 16(3.425,-3.575) 17(3.425,-2.925) 18(3.425,-2.275) 19(3.425,-1.625) 20(3.425,-0.975) 21(3.425,-0.325) 22(3.425,0.325) 23(3.425,0.975) 24(3.425,1.625) 25(3.425,2.275) 26(3.425,2.925) 27(3.425,3.575) 28(3.425,4.225)
MAXIM_90-0096
  rect 1.98x0.53 smd: 1(-2.465,1.905) 2(-2.465,0.635) 3(-2.465,-0.635) 4(-2.465,-1.905) 5(2.465,-1.905) 6(2.465,-0.635) 7(2.465,0.635) 8(2.465,1.905)
MAXIM_90-0113
  rect 1.4x0.35 smd: 1(-2.875,1.95) 2(-2.875,1.3) 3(-2.875,0.65) 4(-2.875,0) 5(-2.875,-0.65) 6(-2.875,-1.3) 7(-2.875,-1.95) 8(2.875,-1.95) 9(2.875,-1.3) 10(2.875,-0.65) 11(2.875,0) 12(2.875,0.65) 13(2.875,1.3) 14(2.875,1.95)
MAXIM_90-0116
  rect 1.4x0.35 smd: 1(-2.875,2.925) 2(-2.875,2.275) 3(-2.875,1.625) 4(-2.875,0.975) 5(-2.875,0.325) 6(-2.875,-0.325) 7(-2.875,-0.975) 8(-2.875,-1.625) 9(-2.875,-2.275) 10(-2.875,-2.925) 11(2.875,-2.925) 12(2.875,-2.275) 13(2.875,-1.625) 14(2.875,-0.975) 15(2.875,-0.325) 16(2.875,0.325) 17(2.875,0.975) 18(2.875,1.625) 19(2.875,2.275) 20(2.875,2.925)
MAXIM_90-0159
  rect 1.5x0.3 smd: 1(-7.7,6) 2(-7.7,5.5) 3(-7.7,5) 4(-7.7,4.5) 5(-7.7,4) 6(-7.7,3.5) 7(-7.7,3) 8(-7.7,2.5) 9(-7.7,2) 10(-7.7,1.5) 11(-7.7,1) 12(-7.7,0.5) 13(-7.7,0) 14(-7.7,-0.5) 15(-7.7,-1) 16(-7.7,-1.5) 17(-7.7,-2) 18(-7.7,-2.5) 19(-7.7,-3) 20(-7.7,-3.5) 21(-7.7,-4) 22(-7.7,-4.5) 23(-7.7,-5) 24(-7.7,-5.5) 25(-7.7,-6) 51(7.7,-6) 52(7.7,-5.5) 53(7.7,-5) 54(7.7,-4.5) 55(7.7,-4) 56(7.7,-3.5) 57(7.7,-3) 58(7.7,-2.5) 59(7.7,-2) 60(7.7,-1.5) 61(7.7,-1) 62(7.7,-0.5) 63(7.7,0) 64(7.7,0.5) 65(7.7,1) 66(7.7,1.5) 67(7.7,2) 68(7.7,2.5) 69(7.7,3) 70(7.7,3.5) 71(7.7,4) 72(7.7,4.5) 73(7.7,5) 74(7.7,5.5) 75(7.7,6)
  rect 0.3x1.5 smd: 26(-6,-7.7) 27(-5.5,-7.7) 28(-5,-7.7) 29(-4.5,-7.7) 30(-4,-7.7) 31(-3.5,-7.7) 32(-3,-7.7) 33(-2.5,-7.7) 34(-2,-7.7) 35(-1.5,-7.7) 36(-1,-7.7) 37(-0.5,-7.7) 38(0,-7.7) 39(0.5,-7.7) 40(1,-7.7) 41(1.5,-7.7) 42(2,-7.7) 43(2.5,-7.7) 44(3,-7.7) 45(3.5,-7.7) 46(4,-7.7) 47(4.5,-7.7) 48(5,-7.7) 49(5.5,-7.7) 50(6,-7.7) 76(6,7.7) 77(5.5,7.7) 78(5,7.7) 79(4.5,7.7) 80(4,7.7) 81(3.5,7.7) 82(3,7.7) 83(2.5,7.7) 84(2,7.7) 85(1.5,7.7) 86(1,7.7) 87(0.5,7.7) 88(0,7.7) 89(-0.5,7.7) 90(-1,7.7) 91(-1.5,7.7) 92(-2,7.7) 93(-2.5,7.7) 94(-3,7.7) 95(-3.5,7.7) 96(-4,7.7) 97(-4.5,7.7) 98(-5,7.7) 99(-5.5,7.7) 100(-6,7.7)
MOD_MAX32625PICO_20P
  round 2.032 hole 2.032 unplated: (-1.27,-10.16) (1.27,-10.16)
  custom 0.445x0.445 smd: 1(-7.62,11.43) 2(-7.62,8.89) 3(-7.62,6.35) 4(-7.62,3.81) 5(-7.62,1.27) 6(-7.62,-1.27) 7(-7.62,-3.81) 8(-7.62,-6.35) 9(-7.62,-8.89) 10(-7.62,-11.43) 11(7.62,-11.43) 12(7.62,-8.89) 13(7.62,-6.35) 14(7.62,-3.81) 15(7.62,-1.27) 16(7.62,1.27) 17(7.62,3.81) 18(7.62,6.35) 19(7.62,8.89) 20(7.62,11.43)
POMONA_3267
  round 12.55 hole 6.55: 1(0,0)
RESC3225X65M
  rect 1.35x2.8 smd: 1(-1.55,0) 2(1.55,0)
SULLINS_PXC02S
  rect 1.7x1.7 hole 1.1: 1(0,0)
  round 1.7 hole 1.1: 2(2.54,0)
SULLINS_PXC03SAAN
  rect 1.75x1.75 hole 1.15: 1(0,0)
  round 1.75 hole 1.15: 2(2.54,0) 3(5.08,0)
SULLINS_PXC04DAAN
  rect 1.75x1.75 hole 1.15: 1(0,0)
  round 1.75 hole 1.15: 2(0,2.54) 3(2.54,0) 4(2.54,2.54) 5(5.08,0) 6(5.08,2.54) 7(7.62,0) 8(7.62,2.54)
SULLINS_PXC04SAAN
  rect 1.75x1.75 hole 1.15: 1(0,0)
  round 1.75 hole 1.15: 2(2.54,0) 3(5.08,0) 4(7.62,0)
SULLINS_PXC05SAAN
  rect 1.75x1.75 hole 1.15: 1(0,0)
  round 1.75 hole 1.15: 2(2.54,0) 3(5.08,0) 4(7.62,0) 5(10.16,0)
SULLINS_PXC07S
  rect 1.7x1.7 hole 1.1: 1(0,0)
  round 1.7 hole 1.1: 2(2.54,0) 3(5.08,0) 4(7.62,0) 5(10.16,0) 6(12.7,0) 7(15.24,0)
SULLINS_PXC08SAAN
  rect 1.75x1.75 hole 1.15: 1(0,0)
  round 1.75 hole 1.15: 2(2.54,0) 3(5.08,0) 4(7.62,0) 5(10.16,0) 6(12.7,0) 7(15.24,0) 8(17.78,0)

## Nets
+5V: C10.2 C25.2 C28.2 C31.2 C34.2 C37.2 C40.2 C43.2 C46.2 C69.2 C70.2 C72.2 C73.2 C76.2 FB5.2 FB6.2 J5.2 J9.1 R10.1 R12.1 R14.1 R16.1 R18.1 R19.1 R20.1 R21.1 R22.1 R23.1 R24.1 R25.1 TP8.1(TP1) TP22.1(TP1) U3.1 U3.2 U3.4 U8.8 U9.8 U10.8 U11.8 U15.1 U15.5 U16.2 U16.15 U16.19
GND: C1.1 C2.2 C3.1 C4.1 C5.1 C6.1 C7.1 C8.1 C9.1 C10.1 C12.1 C13.1 C14.1 C15.1 C16.1 C17.1 C18.1 C19.1 C20.1 C21.1 C22.1 C23.1 C24.1 C25.1 C26.1 C27.1 C28.1 C29.1 C30.1 C31.1 C32.1 C33.1 C34.1 C35.1 C36.1 C37.1 C38.1 C39.1 C40.1 C41.1 C42.1 C43.1 C44.1 C45.1 C46.1 C47.1 C48.1 C61.2 C62.2 C63.1 C64.1 C65.1 C66.1 C67.1 C68.1 C69.1 C70.1 C71.1 C72.1 C73.1 C74.1 C75.1 C76.1 D2.C(K) GND.1 J2.1 J3.2 J4.8 J5.3 J6.2 R1.2 R5.2 R8.2 R11.2 R13.2 R15.2 R17.2 R29.1 R30.2 R51.2 R53.2 R54.2 R55.2 R56.1 R57.1 R60.1 R61.1 R68.2 TP2.1(P) TP6.1(TP1) TP14.1(P) TP21.1(TP1) U1.7 U1.9 U2.7 U2.9 U3.3 U3.5 U3.11 U4.3 U5.3 U6.3 U7.3 U8.3 U8.7 U8.17 U8.19 U8.23 U8.24 U9.3 U9.7 U9.17 U9.19 U9.23 U9.24 U10.3 U10.7 U10.17 U10.19 U10.23 U10.24 U11.3 U11.7 U11.17 U11.19 U11.23 U11.24 U12.29 U12.38 U12.44 U12.57 U13.10 U15.2 U16.1 U16.12 U16.13 U16.18 U16.20
VCC: C1.2 C4.2 C7.2 C63.2 C64.2 FB1.2 FB2.2 J7.1 TP5.1(TP1) U1.1 U1.2 U1.3 U2.1 U2.2 U2.3 U12.17 U12.18 U12.25 U12.49 U12.77 U12.78 U12.79 U12.80 U12.81 U12.82 U12.83 U12.84 U12.93 U12.99 U14.4
VEE: C2.1 C3.2 C27.2 C30.2 C33.2 C36.2 C39.2 C42.2 C45.2 C48.2 C65.2 C66.2 FB3.2 FB4.2 J8.1 TP7.1(TP1) U8.26(VSS) U9.26(VSS) U10.26(VSS) U11.26(VSS) U12.19 U12.20 U12.26 U12.50 U12.76 U12.85 U12.86 U12.87 U12.88 U12.89 U12.90 U12.91 U12.92 U12.100 U14.11
VIN: J14.3 U12.56
VIN_DAC: J15.3 U11.18
VINS: J4.5 U12.55
AMPOUT: AMPOUT.1(TP1) J4.1 U12.94
CB1: C55.1 C58.1 U12.65
CB2: C53.1 U12.66
CB3: C49.1 C50.1 U12.67
CBC: C49.2 C50.2 C53.2 C55.2 C58.2 U12.64
CCH: C51.2 C52.2 U12.71
CCHL: C51.1 C52.1 C54.1 C56.1 U12.70
CCL: C54.2 C56.2 U12.72
CCOMP1: C57.2 U12.74
CCOMP2: C59.2 U12.75
CLH: J14.1 U12.59
CLH1: U8.18 U14.3
CLH_DAC: J15.1 R59.2 U14.1
CLL: J14.2 U12.58
CLL1: U8.25 U14.5
CLL_DAC: J15.2 R58.2 U14.7
DIN: J13.3 U8.11 U10.11 U12.32 U16.8
DIN_PICO: J12.3 U13.15
DOUT: J13.4 U9.9 U11.9 U12.39 U16.11
DOUT1: U8.9 U9.11
DOUT3: U10.9 U11.11
DOUT_PICO: J12.4 U13.14
DUT_NODE: DUT_NODE.1(P) J1.1 R26.1 R27.1 R28.1 R31.2 R32.2 R33.2 R34.2 R35.2 R36.1 R37.2 R38.2 R39.2 R40.1 TP13.1(TP1) U12.14 U12.22
EN: U13.4 U15.8
EXTSEL: J4.7 TP19.1(TP1)
HITMP: HITMP.1(TP1) J11.4 U13.20
HIZMP: J4.4 R49.2 R50.2 U12.30 U13.18
IDDQSEL: J4.6 R46.2 R48.2 U12.31 U13.17
ILIMHI: J11.3 TP18.1(TP1) U13.3
ILIMLO: J11.2 TP17.1(TP1) U13.2
IMEAS: IMEAS.1(TP1) U12.61 U16.3
IOSI: J14.5 U12.53
IOSI_DAC: J15.5 U10.18
IOSV: J14.4 U12.54
IOSV_DAC: J15.4 U10.25
IPAR: J4.3 U12.60
ITHHI: J14.6 U12.52
ITHHI1: U9.18 U14.10
ITHHI_DAC: J15.6 R62.2 U14.8
ITHLO: J14.7 U12.51
ITHLO1: U9.25 U14.12
ITHLO_DAC: J15.7 R63.2 U14.14(OUTD)
LOADB: J13.1 U12.33
LOADB_PICO: J12.1 U13.19
OUT_DAC1: C18.2 TP9.1(TP1) U4.6(OUTS) U4.7 U8.20 U8.22
OUT_DAC2: C20.2 TP10.1(TP1) U5.6(OUTS) U5.7 U9.20 U9.22
OUT_DAC3: C22.2 TP11.1(TP1) U6.6(OUTS) U6.7 U10.20 U10.22
OUT_DAC4: C24.2 TP12.1(TP1) U7.6(OUTS) U7.7 U11.20 U11.22
RA: R31.1 R32.1 R33.1 R34.1 RA.1(TP1) U12.1 U12.2 U12.3 U12.4 U12.5 U12.6 U12.7 U12.8 U12.9
RA_O: R26.2 R27.2 R28.2
RB: R37.1 R38.1 RB.1(TP1) U12.10 U12.11
RC: R35.1 R39.1 RC.1(TP1) U12.12
RD: R36.2 R40.2 RD.1(TP1) U12.13
SAMPO: C57.1 C59.1 U12.73
SCLK: J13.2 U8.10 U9.10 U10.10 U11.10 U12.34 U16.10
SCLK_PICO: J12.2 U13.16
SS_ADC: J12.6 U13.5 U16.7
SS_DAC1: J12.8 U8.5 U8.12 U9.5 U9.12 U13.8(PIN4_7)
SS_DAC3: J12.7 U10.5 U10.12 U11.5 U11.12 U13.6
SS_MAX9959: J13.5 U12.35
SS_MAX9959_PICO: J12.5 U13.13
TEMP: J11.1 TEMP.1 U12.63 U13.1
UNNAMED_1_BANANA_I1_P: D1.C(K) FB1.1 FB2.1 TP1.1(P)
UNNAMED_1_BANANA_I17_P: D3.C(K) FB3.1 FB4.1 R2.2 TP3.1(P)
UNNAMED_1_BANANA_I26_P: FB5.1 FB6.1 R3.2 TP4.1(P)
UNNAMED_1_CAPNP_I37_2: C5.2 U1.5(TIMEOUT)
UNNAMED_1_CAPNP_I53_2: C8.2 U2.5(TIMEOUT)
UNNAMED_1_CAPNP_I66_1: C11.1 U3.8
UNNAMED_1_DIOZENER_I7_A: D1.A R1.1
UNNAMED_1_DIOZENER_I14_A: D2.A R2.1
UNNAMED_1_DIOZENER_I24_A: D3.A R3.1
UNNAMED_1_EVKMAXIMPAD_I8_1: DS6.A J7.2 VCC.1
UNNAMED_1_EVKMAXIMPAD_I29_1: DS11.A J9.2 VDD.1
UNNAMED_1_LED_I77_B: DS6.K(B) R51.1
UNNAMED_1_LED_I85_A: DS8.A R68.1
UNNAMED_1_LED_I85_B: DS8.K(B) J8.2 VEE.1
UNNAMED_1_LED_I88_B: DS10.K(B) R55.1
UNNAMED_1_LED_I91_B: DS9.K(B) R54.1
UNNAMED_1_LED_I97_B: DS11.K(B) R53.1
UNNAMED_1_MAX16910_I32_RESET: R6.2 U1.4
UNNAMED_1_MAX16910_I46_RESET: R9.2 U2.4
UNNAMED_1_MAX16910_I46_SETOV: R7.2 R8.1 U2.6
UNNAMED_1_RESSMD_I39_2: R4.2 R5.1 U1.6
UNNAMED_2_CAPNP_I3_2: C13.2 R10.2 U4.2
UNNAMED_2_CAPNP_I7_2: C17.2 U4.1
UNNAMED_2_CAPNP_I18_2: C19.2 U5.1
UNNAMED_2_CAPNP_I19_2: C14.2 R12.2 U5.2
UNNAMED_2_CAPNP_I33_2: C23.2 U7.1
UNNAMED_2_CAPNP_I35_2: C16.2 R16.2 U7.2
UNNAMED_2_CAPNP_I44_2: C21.2 U6.1
UNNAMED_2_CAPNP_I46_2: C15.2 R14.2 U6.2
UNNAMED_2_MAX5322_I51_CLR: R18.2 U8.6
UNNAMED_2_MAX5322_I51_SHDN: R19.2 U8.4
UNNAMED_2_MAX5322_I73_CLR: R20.2 U9.6
UNNAMED_2_MAX5322_I73_SHDN: R21.2 U9.4
UNNAMED_2_MAX5322_I92_CLR: R22.2 U10.6
UNNAMED_2_MAX5322_I92_SHDN: R23.2 U10.4
UNNAMED_2_MAX5322_I111_CLR: R24.2 U11.6
UNNAMED_2_MAX5322_I111_SHDN: R25.2 U11.4
UNNAMED_2_MAX6126_I1_GNDS: R11.1 U4.4
UNNAMED_2_MAX6126_I13_GNDS: R13.1 U5.4
UNNAMED_2_MAX6126_I25_GNDS: R15.1 U6.4
UNNAMED_2_MAX6126_I50_GNDS: R17.1 U7.4
UNNAMED_2_MAX44245_I130_INA: R57.2 R59.1 U14.2
UNNAMED_2_MAX44245_I131_INB: R56.2 R58.1 U14.6
UNNAMED_2_MAX44245_I132_INC: R60.2 R62.1 U14.9
UNNAMED_2_MAX44245_I133_IND: R61.2 R63.1 U14.13
UNNAMED_5_CAPNP_I49_1: C62.1 U12.23
UNNAMED_5_CAPNP_I51_1: C61.1 U12.24
UNNAMED_5_CAPNP_I147_1: C60.1 U12.69
UNNAMED_5_CAPNP_I147_2: C60.2 U12.68
UNNAMED_5_CAPNP_I155_2: C68.2 U15.6(VP)
UNNAMED_5_CAPNP_I158_2: C67.2 U15.3 U15.9
UNNAMED_5_CAPNP_I169_2: C75.2 U16.17
UNNAMED_5_CAPNP_I171_2: C74.2 U16.16
UNNAMED_5_EKMAX32010_I1_21: U12.21 VRXP.1(TP1)
UNNAMED_5_EKMAX32010_I1_40: EXTSEL.1(TP1) U12.40
UNNAMED_5_EKMAX32010_I1_41: HITEMP.1(TP1) R45.2 R47.2 U12.41
UNNAMED_5_EKMAX32010_I1_42: ILIMLO.1(TP1) R43.2 R44.2 U12.42
UNNAMED_5_EKMAX32010_I1_43: ILIMHI.1(TP1) R41.2 R42.2 U12.43
UNNAMED_5_HEADER2P_I37_2: J1.2 U12.15
UNNAMED_5_HEADER2P_I38_2: J2.2 U12.16
UNNAMED_5_HEADER2P_I71_1: J3.1 R29.2 R30.1 U12.36 VTHR.1(TP1)
UNNAMED_5_HEADER2P_I160_1: J6.1 U15.4
UNNAMED_5_LED_I57_B: DS5.K(B) R50.1
UNNAMED_5_LED_I62_B: DS4.K(B) R48.1
UNNAMED_5_LED_I83_B: DS3.K(B) R47.1
UNNAMED_5_LED_I91_B: DS2.K(B) R44.1
UNNAMED_5_LED_I97_B: DS1.K(B) R42.1
VDAC1: C6.2 C26.2 C29.2 C38.2 C41.2 DS9.A R4.1 R6.1 U1.8 U8.21 U9.21 VDAC.1(TP1)
VDAC2: C9.2 C32.2 C35.2 C44.2 C47.2 R7.1 R9.1 U2.8 U10.21 U11.21
VL: C11.2 C12.2 C71.2 DS1.A DS2.A DS3.A DS4.A DS5.A DS10.A R41.1 R43.1 R45.1 R46.1 R49.1 U3.7 U3.9 U3.10 U12.37 U16.14 VL.1(TP1)
VMEAS: U12.62 U16.4 VMEAS.1(TP1)
VTHR: J4.2 TP20.1(TP1)

Pads without a net: J5 1; U3 6; U4 5 8; U5 5 8; U6 5 8; U7 5 8; U8 1 2 13 14 15 16 27 28; U9 1 2 13 14 15 16 27 28; U10 1 2 13 14 15 16 27 28; U11 1 2 13 14 15 16 25 27 28; U12 27 28 45 46 47 48 95 96 97 98; U13 7 9 11 12; U15 7; U16 5 6 9

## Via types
v1: diameter 0.508, hole 0.254, TOP to BOTTOM, 262 vias

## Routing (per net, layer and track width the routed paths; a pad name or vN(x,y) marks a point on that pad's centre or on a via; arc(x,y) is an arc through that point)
+5V: length 51.7
  TOP w0.254: U15.5 142.34,98.71 C69.2
  TOP w0.305: U15.1 v1(145.75,95.43)
  TOP w0.356: v1(105.84,55.12) 105.07,54.35 U16.19 ; U16.15 105.74,51.74 v1(105.92,51.56) ; C70.2 96.01,53.95 96.4,54.35 U16.2
  TOP w0.381: U8.8 v1(132.15,20.07) ; U10.8 v1(132.15,55.63) ; U9.8 v1(132.15,37.85) ; U11.8 v1(132.15,73.41)
  TOP w0.508: R23.1 v1(127.43,53.7) ; R18.1 v1(130.94,16.94) ; R16.1 v1(118.87,71.68) ; R21.1 v1(129.54,34.72) ; R24.1 v1(132.21,71.22) ; R12.1 v1(119.63,35.74) ; C72.2 106.55,50.93 v1(105.92,51.56) ; v1(141.35,100.08) C69.2 ; R22.1 v1(132.21,53.7) ; R14.1 v1(118.87,53.9) ; R25.1 v1(127.43,71.22) ; R20.1 v1(130.94,34.72) ; R10.1 v1(119.63,17.96) ; R19.1 v1(129.54,16.94) ; v1(94.41,53.95) C70.2 ; C73.2 v1(105.84,55.12)
  TOP w0.635: J5.2 TP22.1
  BOTTOM w0.508: v1(132.15,20.07) 132.61,20.53 C25.2 C37.2 ; C46.2 C34.2 132.61,73.87 v1(132.15,73.41) ; v1(132.15,55.63) 132.61,56.09 C31.2 C43.2 ; v1(132.15,37.85) 132.61,38.31 C28.2 C40.2
GND: length 172.7
  TOP w0.254: v1(69.72,52.32) 69.98,52.07 U12.38 ; U12.29 v1(69.72,47.57) ; v1(69.72,55.07) U12.44 ; U3.3 v1(38.73,94.23) ; U3.5 38.12,93.23 v1(38.23,93.34) ; U12.57 v1(66.5,58.17)
  TOP w0.356: U2.7 41.08,16.96 v1(41.27,16.76) ; U16.18 105.38,53.7 v1(105.54,53.85) ; v1(105.03,55.5) 104.53,55 U16.20 ; U16.12 105.28,49.79 v1(105.28,49.79) 105.28,50.09 104.93,50.44 U16.13 ; C70.1 96.11,55.52 96.64,55 U16.1 ; v1(146.69,96.52) 146.25,96.96 U15.2 ; U1.7 41.08,23.57 v1(41.27,23.37)
  TOP w0.381: U11.23 130.85,80.84 v1(130.53,80.52) 130.2,80.85 U11.24 ; U9.23 130.85,45.28 v1(130.53,44.96) 130.2,45.29 U9.24 ; U8.3 v1(128.9,23.5) ; U10.19 133.48,64.42 133.48,65.79 133.86,66.17 v1(134.11,66.17) 134.34,66.17 134.72,65.79 134.72,64.42 U10.17 ; U6.3 v1(118.44,57.6) ; U9.7 v1(131.5,41.35) ; U8.23 130.85,27.5 v1(130.53,27.18) 130.2,27.51 U8.24 ; U8.19 133.45,27.73 133.75,27.43 v1(134.11,27.43) 134.37,27.43 134.75,27.81 U8.17 ; U9.19 133.45,45.51 133.75,45.21 v1(134.11,45.21) 134.37,45.21 134.75,45.59 U9.17 ; U9.3 v1(128.9,41.27) ; U10.24 130.2,63.07 v1(130.53,62.74) 130.85,63.06 U10.23 ; U10.7 v1(131.5,59.13) ; U11.7 v1(131.5,76.91) ; U7.3 v1(118.44,75.38) ; U10.3 v1(128.9,59.05) ; U8.7 v1(131.5,23.57) ; U11.19 133.45,81.07 133.75,80.77 v1(134.11,80.77) 134.37,80.77 134.75,81.15 U11.17 ; U11.3 v1(128.9,76.83)
  TOP w0.508: C12.1 v1(45.09,95.25) ; v1(39.12,18.36) 39.12,18.44 C7.1 ; C14.1 v1(118.24,35.74) ; C20.1 v1(121.54,48.26) ; R55.2 v1(42.52,100.2) ; C15.1 v1(117.47,53.9) ; C2.2 31.75,53.52 v1(31.75,53.47) ; C72.1 v1(110.24,50.93) ; R15.2 v1(120.27,53.9) ; C5.1 v1(38.15,20.7) ; C61.2 v1(77.6,25.91) ; R54.2 v1(42.39,29.46) ; C24.1 v1(120.09,83.19) ; R53.2 v1(31.75,84.58) ; C4.1 39.24,25.04 v1(39.24,25.02) ; C1.1 v1(25.09,26.75) ; U5.3 v1(119.63,42.16) ; C68.1 v1(139.17,98.88) ; R11.2 v1(121.03,17.96) ; C9.1 v1(46.35,17.4) ; C10.1 v1(38.38,97.64) ; C8.1 v1(38.28,14.91) ; R51.2 v1(33.15,27.69) ; R60.1 v1(149.1,38.66) ; R57.1 v1(142.24,29.92) ; C66.1 v1(145.67,42.16) ; C6.1 v1(46.35,24) ; R30.2 89.28,53.21 90.93,51.56 J3.2 90.93,49.7 90.13,48.9 R29.1 ; R17.2 v1(120.27,71.68) ; C23.1 v1(116.08,71.68) ; U4.3 v1(119.63,24.38) ; R13.2 v1(121.03,35.74) ; C69.1 v1(144.86,100.08) ; C75.1 v1(110.24,53.72) ; v1(94.41,55.52) C70.1 ; C71.1 v1(110.24,49.53) ; C74.1 v1(110.24,52.32) ; C17.1 v1(115.44,24.33) ; C67.1 147.35,95.86 v1(146.69,96.52) ; C64.1 v1(145.67,26.42) ; R5.2 v1(46.35,22.48) ; C62.2 v1(76.2,25.91) ; R68.2 v1(39.19,53.72) ; C13.1 v1(118.24,17.96) ; R56.1 v1(149.1,29.92) ; C3.1 v1(27.3,80.14) ; C21.1 v1(116.08,53.9) ; C16.1 v1(117.47,71.68) ; R61.1 v1(142.24,38.66) ; R8.2 v1(46.35,15.88) ; C76.1 v1(23.37,84.33) ; C19.1 v1(115.44,42.11) ; C73.1 v1(110.24,55.12) ; C22.1 v1(120.09,65.41) ; C18.1 v1(121.54,30.48)
  TOP w0.635: TP21.1 138.18,111.63 133.86,111.63
  BOTTOM w0.508: C45.1 v1(126.42,64.01) ; C30.1 v1(126.42,47.62) ; C26.1 C38.1 v1(130.53,27.18) ; C33.1 v1(126.42,65.41) ; v1(130.53,44.96) C41.1 C29.1 ; C36.1 v1(126.42,83.19) ; C34.1 C46.1 131.04,76.44 v1(131.5,76.91) ; v1(131.5,59.13) 131.04,58.66 C43.1 C31.1 ; C25.1 C37.1 131.04,23.1 v1(131.5,23.57) ; C35.1 C47.1 v1(130.53,80.52) ; C32.1 C44.1 v1(130.53,62.74) ; C27.1 v1(126.42,29.84) ; C64.1 v1(145.67,26.42) ; C39.1 v1(126.42,28.45) ; C28.1 C40.1 131.04,40.88 v1(131.5,41.35) ; C66.1 v1(145.67,42.16) ; C42.1 v1(126.42,46.23) ; C48.1 v1(126.42,81.79)
  vias: v1(38.23,95.12) v1(38.23,24.13) v1(38.23,22.35) v1(38.23,17.53) v1(38.23,15.75) v1(38.73,23.24) v1(38.73,16.64) v1(39.24,95.12) v1(39.24,93.34) v1(39.24,24.13) v1(39.24,22.35) v1(39.24,17.53) v1(39.24,15.75)
VCC: length 12.5
  TOP w0.254: v1(69.5,45.85) U12.25 ; v1(57.28,46.57) U12.99 ; v1(57.28,49.57) U12.93 ; U12.18 66,45.63 v1(65.79,45.85) 65.5,45.56 U12.17 ; v1(69.72,57.57) U12.49
  TOP w0.305: U14.4 v1(145.67,29.96)
  TOP w0.508: C64.2 v1(145.67,29.96)
  BOTTOM w0.508: C64.2 v1(145.67,29.96)
  vias: v1(57.28,57.53) v1(57.28,56.77) v1(57.28,55.88) v1(57.28,54.99) v1(57.28,54.23)
VEE: length 27.9
  TOP w0.254: v1(72.33,58.61) 71.79,58.07 U12.50 ; v1(72.33,45.53) 71.79,46.07 U12.26 ; U12.100 55.21,46.07 v1(54.67,45.53) ; U12.19 66.5,43.11 v1(66.71,42.89) 67,43.18 U12.20 ; v1(54.59,58.07) U12.76
  TOP w0.305: U14.11 v1(145.67,38.62)
  TOP w0.381: U10.26 v1(128.9,62.99) ; v1(128.93,27.3) 128.9,27.33 U8.26 ; v1(128.93,80.64) 128.9,80.67 U11.26 ; U9.26 128.9,45.11 v1(128.93,45.09)
  TOP w0.508: C66.2 v1(145.67,38.62)
  BOTTOM w0.508: v1(128.93,80.64) C48.2 C36.2 ; C30.2 C42.2 v1(128.93,45.09) ; v1(128.9,62.99) 128.93,63.02 C45.2 C33.2 ; C27.2 C39.2 v1(128.93,27.3) ; C66.2 v1(145.67,38.62)
  vias: v1(54.1,53.47) v1(54.1,52.7) v1(54.1,51.82) v1(54.1,50.93) v1(54.1,50.16)
VIN: length 44.7
  TOP w0.254: U12.56 67,60.77 66.56,61.21 66.56,63 72.9,69.34 103.76,69.34 J14.3
VIN_DAC: length 50.9
  TOP w0.254: v1(137.54,69.22) 137.41,69.34 108.33,69.34 J15.3 ; v1(137.54,84.2) 134.49,84.2 134.1,83.81 U11.18
  BOTTOM w0.254: v1(137.54,84.2) v1(137.54,69.22)
VINS: length 32.3
  TOP w0.254: v1(67.18,61.47) 67.5,61.15 U12.55
  BOTTOM w0.254: J4.5 86.36,75.44 79.25,68.33 79.25,64.39 76.33,61.47 v1(67.18,61.47)
AMPOUT: length 73.4
  TOP w0.254: AMPOUT.1 38.02,49.07 U12.94
  BOTTOM w0.254: J4.1 75.69,73.03 64.06,73.03 40.05,49.02 AMPOUT.1
CB1: length 18.6
  TOP w0.254: C58.1 C55.1 64.14,71.5 62.5,69.87 U12.65
CB2: length 16.8
  TOP w0.254: C53.1 61.34,70.48 62,69.83 U12.66
CB3: length 18.6
  TOP w0.254: C49.1 C50.1 59.94,70.87 61.5,69.31 U12.67
CBC: length 25.3
  TOP w0.254: U12.64 63,69.48 65.02,71.5 65.02,77.62 64.77,77.88 C55.2 C58.2 C53.2 C50.2 C49.2
CCH: length 19.7
  TOP w0.254: U12.71 59.5,67.12 55.12,71.5 C52.2 C51.2
CCHL: length 24.6
  TOP w0.254: C54.1 C56.1 C51.1 C52.1 55.63,77.88 55.88,77.62 55.88,71.88 60,67.76 U12.70
CCL: length 20.7
  TOP w0.254: C54.2 C56.2 52.32,73.28 59,66.6 U12.72
CCOMP1: length 20.2
  TOP w0.254: U12.74 58,65.57 49.15,74.42 C57.2
CCOMP2: length 20.6
  TOP w0.254: C59.2 47.75,74.93 57.5,65.18 U12.75
CLH: length 48.1
  TOP w0.254: U12.59 65.5,63.72 72.14,70.36 99.69,70.36 J14.1
CLH1: length 19.2
  TOP w0.254: U8.18 134.1,30.34 134.37,30.61 136.78,30.61 141.22,26.16 144.27,26.16 144.87,26.76 144.87,29.59 145.02,29.74 U14.3
CLH_DAC: length 85.8
  TOP w0.254: v1(139.83,69.72) 139.19,70.36 112.39,70.36 J15.1 ; R59.2 v1(143.64,29.93) 143.72,30.01 U14.1
  BOTTOM w0.254: v1(139.83,69.72) 142.24,67.31 142.24,52.08 149.87,44.45 149.87,32.88 147.6,30.61 144.31,30.61 v1(143.64,29.93)
CLL: length 46.3
  TOP w0.254: U12.58 66,63.33 72.52,69.85 101.73,69.85 J14.2
CLL1: length 25
  TOP w0.254: U8.25 129.55,27.56 129.55,27.56 129.55,26.91 130.18,26.29 140.08,26.29 140.84,25.53 145.8,25.53 146.5,26.23 146.5,27.48 146.47,27.51 146.47,29.59 146.32,29.74 U14.5
CLL_DAC: length 82.2
  TOP w0.254: U14.7 v1(147.62,29.92) 147.62,29.06 R58.2 ; v1(141.48,69.02) 139.26,69.02 138.43,69.85 110.36,69.85 J15.2
  BOTTOM w0.254: v1(141.48,69.02) 142.84,67.66 142.84,52.61 150.37,45.09 150.37,32.67 v1(147.62,29.92)
DIN: length 183.7
  TOP w0.254: v1(135,55.5) 134.1,56.4 U10.11 ; v1(135.44,51.56) 115.82,51.56 111.39,47.13 99.2,47.13 97.79,45.72 v1(95.12,45.72) 81.27,45.72 77.92,49.07 U12.32 ; U8.11 v1(134.1,23.5) ; U16.8 95.77,50.44 95.75,50.42 v1(95.12,50.42)
  BOTTOM w0.254: v1(135,55.5) 135.44,55.06 v1(135.44,51.56) 135.44,44.76 134.11,43.43 134.11,42.67 135.37,41.41 135.37,27.55 134.1,26.28 v1(134.1,23.5) ; J13.3 101.93,97.99 101.57,97.99 100.15,99.41 99.79,99.41 99.43,99.05 99.43,98.69 100.85,97.28 100.85,96.92 100.49,96.56 100.13,96.56 98.72,97.98 98.36,97.98 98,97.62 98,97.26 99.42,95.84 99.42,95.48 99.06,95.12 98.7,95.12 97.28,96.54 96.92,96.54 96.56,96.18 96.56,95.82 97.98,94.4 97.98,94.04 97.62,93.68 97.26,93.68 95.84,95.1 95.48,95.1 95.12,94.74 95.12,94.38 96.54,92.96 96.54,92.6 95.63,91.69 95.63,90.93 96.01,90.55 96.01,89.79 95.63,89.41 95.63,88.54 96.01,88.16 96.01,51.93 95.12,51.04 v1(95.12,50.42) v1(95.12,45.72)
DIN_PICO: length 14.3
  TOP w0.254: U13.15 107.95,101.47 J12.3
DOUT: length 183.6
  TOP w0.254: U12.39 76.7,52.57 78.49,54.36 89.79,54.36 96.01,48.13 101.92,48.13 v1(102.4,48.61) 102.94,49.14 U16.11 104.49,49.14 105.51,48.12 110.86,48.12 115.57,52.83 132.84,52.83 v1(133.48,53.47) ; U11.9 v1(132.8,77.85) ; J13.4 100.84,99.44 100.84,89.19 v1(102.4,87.63) ; U9.9 v1(132.8,42.42)
  BOTTOM w0.254: v1(102.4,48.61) 102.4,78.16 102.65,78.42 104.65,78.42 104.9,78.67 104.9,79.18 104.65,79.43 102.65,79.43 102.4,79.69 102.4,80.2 102.65,80.45 104.65,80.45 104.9,80.7 104.9,81.21 104.65,81.47 102.65,81.47 102.4,81.72 102.4,82.23 102.65,82.48 104.65,82.48 104.9,82.74 104.9,83.24 104.65,83.5 102.65,83.5 102.4,83.75 102.4,84.26 102.65,84.51 104.65,84.51 104.9,84.77 104.9,85.28 104.65,85.53 102.65,85.53 102.4,85.78 v1(102.4,87.63) ; v1(132.8,42.42) 132.8,43.04 132.95,43.19 132.95,51.74 133.48,52.27 v1(133.48,53.47) 133.48,72.77 134.72,74.02 134.72,77.11 133.99,77.85 v1(132.8,77.85)
DOUT1: length 21.4
  TOP w0.254: U8.9 v1(132.8,24.64) ; U9.11 v1(134.1,41.27)
  BOTTOM w0.254: v1(134.1,41.27) 134.1,37.62 133.48,36.99 133.48,25.31 v1(132.8,24.64)
DOUT3: length 21.4
  TOP w0.254: U10.9 v1(132.8,60.07) ; U11.11 v1(134.1,76.83)
  BOTTOM w0.254: v1(132.8,60.07) 132.8,60.72 132.98,60.9 132.98,73.04 134.1,74.16 v1(134.1,76.83)
DOUT_PICO: length 14.3
  TOP w0.254: J12.4 107.95,104.01 U13.14
DUT_NODE: length 3
  TOP w0.254: v1(68,45.85) U12.22 ; v1(64,45.85) U12.14
EN: length 9
  TOP w0.254: U13.4 142.03,96.39 142.11,96.31 U15.8
EXTSEL: length 5.7
  TOP w0.254: J4.7 TP19.1
HITMP: length 48.3
  TOP w0.254: U13.20 HITMP.1 ; v1(135.76,95.25) 144.02,95.25 147.7,91.57 J11.4
  BOTTOM w0.254: v1(135.76,95.25) 118.49,95.25 HITMP.1
HIZMP: length 116.5
  TOP w0.254: U12.30 72.2,48.07 72.96,47.31 72.96,45.34 72.96,45.33 72.96,44.65 v1(73.91,43.69) 78.87,43.69 79.68,44.5 99.36,44.5 v1(101.09,46.23) ; J4.4 86.36,83.69 v1(101.09,83.69) ; 118.62,93.85 v1(113.41,93.85)
  BOTTOM w0.254: v1(101.09,46.23) v1(101.09,83.69) 101.09,88.01 103.55,90.47 110.03,90.47 v1(113.41,93.85) ; v1(73.91,43.69) R50.2 R49.2
IDDQSEL: length 112.6
  TOP w0.254: v1(99.57,46.23) 98.42,45.09 81.16,45.09 78.5,47.75 73.53,47.75 v1(72.9,48.39) 72.72,48.57 U12.31 ; v1(99.57,82.93) 88.14,82.93 J4.6 ; U13.17 v1(113.41,96.39)
  BOTTOM w0.254: v1(72.9,48.39) 73.53,47.75 73.71,47.75 73.72,47.75 74.09,47.75 74.09,47.75 R48.2 R46.2 ; v1(99.57,46.23) v1(99.57,82.93) 99.57,88.39 102.87,91.69 108.71,91.69 v1(113.41,96.39)
ILIMHI: length 17.6
  TOP w0.254: J11.3 146.18,89.03 TP18.1 141.35,93.85 133.86,93.85
ILIMLO: length 19.2
  TOP w0.254: J11.2 146.18,86.49 TP17.1 137.54,91.31 U13.2
IMEAS: length 55.5
  TOP w0.254: v1(71.88,64.14) 74.25,66.5 92.5,66.5 IMEAS.1 95.76,63.25 95.76,58.04 93.73,56.01 93.73,53.72 94.36,53.09 96.3,53.09 96.91,53.7 U16.3 ; U12.61 v1(64.5,58.18)
  BOTTOM w0.254: v1(71.88,64.14) 66.24,64.14 64.5,62.4 v1(64.5,58.18)
IOSI: length 43.1
  TOP w0.254: U12.53 68.5,63.29 73.53,68.33 101.73,68.33 J14.5
IOSI_DAC: length 36.6
  TOP w0.254: v1(124.97,61.72) 133.22,61.72 134.1,62.6 U10.18 ; v1(124.97,68.2) 110.24,68.2 J15.5
  BOTTOM w0.254: v1(124.97,61.72) v1(124.97,68.2)
IOSV: length 43.2
  TOP w0.254: U12.54 68,63.68 73.15,68.83 103.76,68.83 J14.4
IOSV_DAC: length 30.9
  TOP w0.254: U10.25 129.55,63.12 129.55,63.12 129.55,62.61 129.3,62.36 v1(125.6,62.36) ; J15.4 108.32,68.82 125.49,68.82 v1(125.6,68.71)
  BOTTOM w0.254: v1(125.6,62.36) v1(125.6,68.71)
IPAR: length 29.1
  TOP w0.254: U12.60 65,63.98 72.01,70.99 76.2,70.99 J4.3
ITHHI: length 43
  TOP w0.254: U12.52 69,62.85 73.97,67.82 99.69,67.82 J14.6
ITHHI1: length 21.8
  TOP w0.254: U9.18 134.1,48.01 134.48,48.39 140.84,48.39 146.38,42.85 146.38,38.98 146.32,38.92 U14.10
ITHHI_DAC: length 67.2
  TOP w0.254: R62.2 147.7,38.74 v1(147.62,38.66) U14.8 ; J15.6 112.07,67.5 136.72,67.5 v1(140.84,63.37)
  BOTTOM w0.254: v1(147.62,38.66) 147.62,44.96 140.84,51.73 v1(140.84,63.37)
ITHLO: length 43
  TOP w0.254: U12.51 69.5,62.64 74.17,67.31 97.66,67.31 J14.7
ITHLO1: length 23.6
  TOP w0.254: U14.12 145.02,38.5 144.91,38.61 144.91,42.67 143.51,44.07 130.31,44.07 129.55,44.83 129.55,45.45 129.55,45.45 U9.25
ITHLO_DAC: length 71.5
  TOP w0.254: R63.2 v1(143.64,38.66) 143.72,38.58 U14.14 ; J15.7 111.38,64.26 111.38,64.9 113.48,67 136.33,67 v1(139.95,63.37)
  BOTTOM w0.254: v1(139.95,63.37) 139.95,51.59 146.97,44.58 146.97,38.38 146.58,38 144.3,38 v1(143.64,38.66)
LOADB: length 77.2
  TOP w0.254: v1(97.85,46.93) 97.28,46.35 81.34,46.35 78.12,49.57 U12.33
  BOTTOM w0.254: v1(97.85,46.93) 98.55,47.62 98.55,89.53 J13.1
LOADB_PICO: length 14.3
  TOP w0.254: U13.19 107.95,91.31 J12.1
OUT_DAC1: length 29.8
  TOP w0.381: U8.22 v1(131.5,30.73) 132.36,30.73 132.8,30.29 U8.20
  TOP w0.508: C18.2 118.36,29.87 U4.7 ; C18.2 TP9.1 ; C18.2 118.97,31.47 119.38,31.88 130.36,31.88 v1(131.5,30.73) ; C18.2 118.97,30.22 119.63,29.56 U4.6
OUT_DAC2: length 30.1
  TOP w0.381: U9.22 v1(131.5,48.51) 132.36,48.51 132.8,48.07 U9.20
  TOP w0.508: TP10.1 116.2,48.26 C20.2 ; v1(131.5,48.51) 130.87,49.15 119.38,49.15 118.97,48.74 C20.2 ; C20.2 118.36,47.65 U5.7 ; C20.2 118.97,48 119.63,47.34 U5.6
OUT_DAC3: length 26.9
  TOP w0.381: U10.22 v1(131.5,66.29) 132.36,66.29 132.8,65.85 U10.20 ; U6.6 118.44,64.06 v1(118.11,64.39) 117.78,64.06 U6.7
  TOP w0.508: v1(131.5,66.29) 118.08,66.29 117.58,65.79 C22.2 ; v1(118.11,64.39) 117.58,64.92 C22.2 ; TP11.1 115.06,65.41 C22.2
OUT_DAC4: length 27.7
  TOP w0.381: U7.7 117.78,81.84 v1(118.11,82.17) 118.44,81.84 U7.6 ; U11.22 v1(131.5,84.07) 132.36,84.07 132.8,83.63 U11.20
  TOP w0.508: C24.2 117.58,82.7 v1(118.11,82.17) ; C24.2 TP12.1 ; C24.2 117.58,84.3 118.11,84.84 130.74,84.84 v1(131.5,84.07)
RB: length 51.7
  TOP w0.254: U12.10 62,43.11 v1(62.21,42.89) 62.5,43.18 U12.11
  TOP w0.508: v1(62.21,42.89) 62.21,42.14 61.98,41.91 61.98,40.51 64.52,37.97 R37.1
  TOP w0.762: R37.1 R38.1
  BOTTOM w0.508: RB.1 53.18,21.5 53.18,37.17 58.89,42.89 v1(62.21,42.89)
RC: length 60.4
  TOP w0.254: U12.12 63,41.29
  TOP w0.508: v1(63,41.29) 63,41.29 70.99,33.3 R35.1
  BOTTOM w0.508: RC.1 54.36,25.4 54.36,36.7 59.69,42.04 62.25,42.04 v1(63,41.29) 60.58,38.87 R39.1
RD: length 40.6
  TOP w0.254: v1(63.75,42.16) 63.5,42.42 U12.13
  TOP w0.508: RD.1 73.79,23.75 73.79,27.97 73.28,28.47 R36.2 72.39,33.53 v1(63.75,42.16)
  BOTTOM w0.508: v1(63.75,42.16) 63.75,40.51 62.1,38.86 R40.2
SAMPO: length 23.7
  TOP w0.254: U12.73 58.5,66.09 50.04,74.55 50.04,77.62 49.78,77.88 C57.1 C59.1
SCLK: length 183.9
  TOP w0.254: U8.10 v1(133.45,20.07) ; U9.10 v1(133.45,37.85) ; U11.10 133.45,73.81 v1(134.87,72.39) ; v1(134.11,55.5) 133.45,56.16 U10.10 ; U16.10 v1(96.4,49.14) ; v1(134.11,52.2) 115.7,52.2 111.12,47.62 97.03,47.62 v1(96.39,46.99) 81.41,46.99 78.33,50.07 U12.34
  BOTTOM w0.254: v1(96.39,46.99) 96.39,47.61 96.4,47.62 v1(96.4,49.14) 97.54,50.28 97.54,91.06 J13.2 ; v1(133.45,20.07) 133.45,23.09 132.17,24.37 132.17,24.98 132.97,25.78 132.97,37.36 v1(133.45,37.85) 133.45,51.54 v1(134.11,52.2) v1(134.11,55.5) 134.87,56.26 134.87,71.76 134.87,71.77 v1(134.87,72.39)
SCLK_PICO: length 14.3
  TOP w0.254: J12.2 107.95,98.93 U13.16
SS_ADC: length 94.5
  TOP w0.254: U16.7 v1(96.52,51.09) ; J12.6 101.85,106.55 99.44,104.14 99.44,94.49 v1(96.65,91.69) ; U13.5 v1(130.43,98.93)
  BOTTOM w0.254: v1(130.43,98.93) 114.68,98.93 107.06,106.55 J12.6 ; v1(96.52,51.09) 96.52,91.57 v1(96.65,91.69)
SS_DAC1: length 138.9
  TOP w0.254: U9.12 v1(134.75,43.05) 131.06,43.05 130.2,42.19 U9.5 ; U8.12 v1(134.75,25.27) 131.06,25.27 130.2,24.41 U8.5 ; v1(137.29,106.55) U13.8 v1(130.43,106.55)
  BOTTOM w0.254: J12.8 107.06,111.63 112.14,106.55 v1(130.43,106.55) ; v1(137.29,106.55) 137.29,92.08 135.64,90.42 135.64,55.75 136.14,55.24 136.14,44.45 v1(134.75,43.05) 135.87,41.93 135.87,27.29 134.75,26.17 v1(134.75,25.27)
SS_DAC3: length 102.7
  TOP w0.254: U10.5 130.2,59.97 130.94,60.71 v1(136.27,60.71) 134.75,59.19 U10.12 ; U11.12 134.75,77.22 v1(136.27,78.74) 131.19,78.74 130.2,77.75 U11.5 ; v1(130.43,101.47) U13.6 v1(137.92,101.47)
  BOTTOM w0.254: v1(136.27,60.71) v1(136.27,78.74) 136.27,90.17 137.92,91.82 v1(137.92,101.47) ; v1(130.43,101.47) 114.68,101.47 107.06,109.09 J12.7
SS_MAX9959: length 84.2
  TOP w0.254: U12.35 78.56,50.57 81.5,47.62 v1(93.34,47.62)
  BOTTOM w0.254: v1(93.34,47.62) 93.34,57.53 92.71,58.17 92.71,93.85 J13.5
SS_MAX9959_PICO: length 14.3
  TOP w0.254: J12.5 107.95,106.55 U13.13
TEMP: length 115.5
  TOP w0.254: J11.1 147.7,82.17 143,82.17 136.4,88.77 U13.1 133.86,87 133.29,86.43 68.01,86.43 65.66,84.07 TEMP.1 65.66,71.25 63.5,69.09 U12.63
UNNAMED_1_CAPNP_I37_2: length 1.8
  TOP w0.254: C5.2 40.67,21.81 U1.5
UNNAMED_1_CAPNP_I53_2: length 1.9
  TOP w0.254: C8.2 40.67,15.41 40.41,15.66 U2.5
UNNAMED_1_CAPNP_I66_1: length 2.6
  TOP w0.254: U3.8 41.66,94.23 42.42,93.47 C11.1
UNNAMED_1_LED_I77_B: length 1.7
  TOP w0.762: DS6.K 28.95,27.57 R51.1
UNNAMED_1_LED_I85_A: length 1.7
  TOP w0.762: R68.1 36.57,53.83 DS8.A
UNNAMED_1_LED_I85_B: length 9.4
  TOP w0.762: VEE.1 J8.2 38.73,55.74 DS8.K
UNNAMED_1_LED_I88_B: length 2.1
  TOP w0.762: R55.1 44.21,99.2 DS10.K
UNNAMED_1_LED_I91_B: length 1.7
  TOP w0.762: DS9.K 44.08,28.46 R54.1
UNNAMED_1_LED_I97_B: length 1.7
  TOP w0.762: R53.1 29.07,84.69 DS11.K
UNNAMED_1_MAX16910_I32_RESET: length 14.2
  TOP w0.254: U1.4 v1(36.25,22.27) ; R6.2 v1(44.96,25.27)
  BOTTOM w0.254: v1(36.25,22.27) 36.25,25.08 37.14,25.97 44.26,25.97 v1(44.96,25.27)
UNNAMED_1_MAX16910_I46_RESET: length 13.9
  TOP w0.254: v1(36.2,15.37) 36.49,15.66 U2.4 ; R9.2 v1(44.96,18.92)
  BOTTOM w0.254: v1(36.2,15.37) 36.2,17.02 38.73,19.56 44.32,19.56 v1(44.96,18.92)
UNNAMED_1_MAX16910_I46_SETOV: length 3.8
  TOP w0.356: R7.2 41.22,15.85 40.76,16.31 U2.6
  TOP w0.762: R7.2 42.32,15.88 R8.1
